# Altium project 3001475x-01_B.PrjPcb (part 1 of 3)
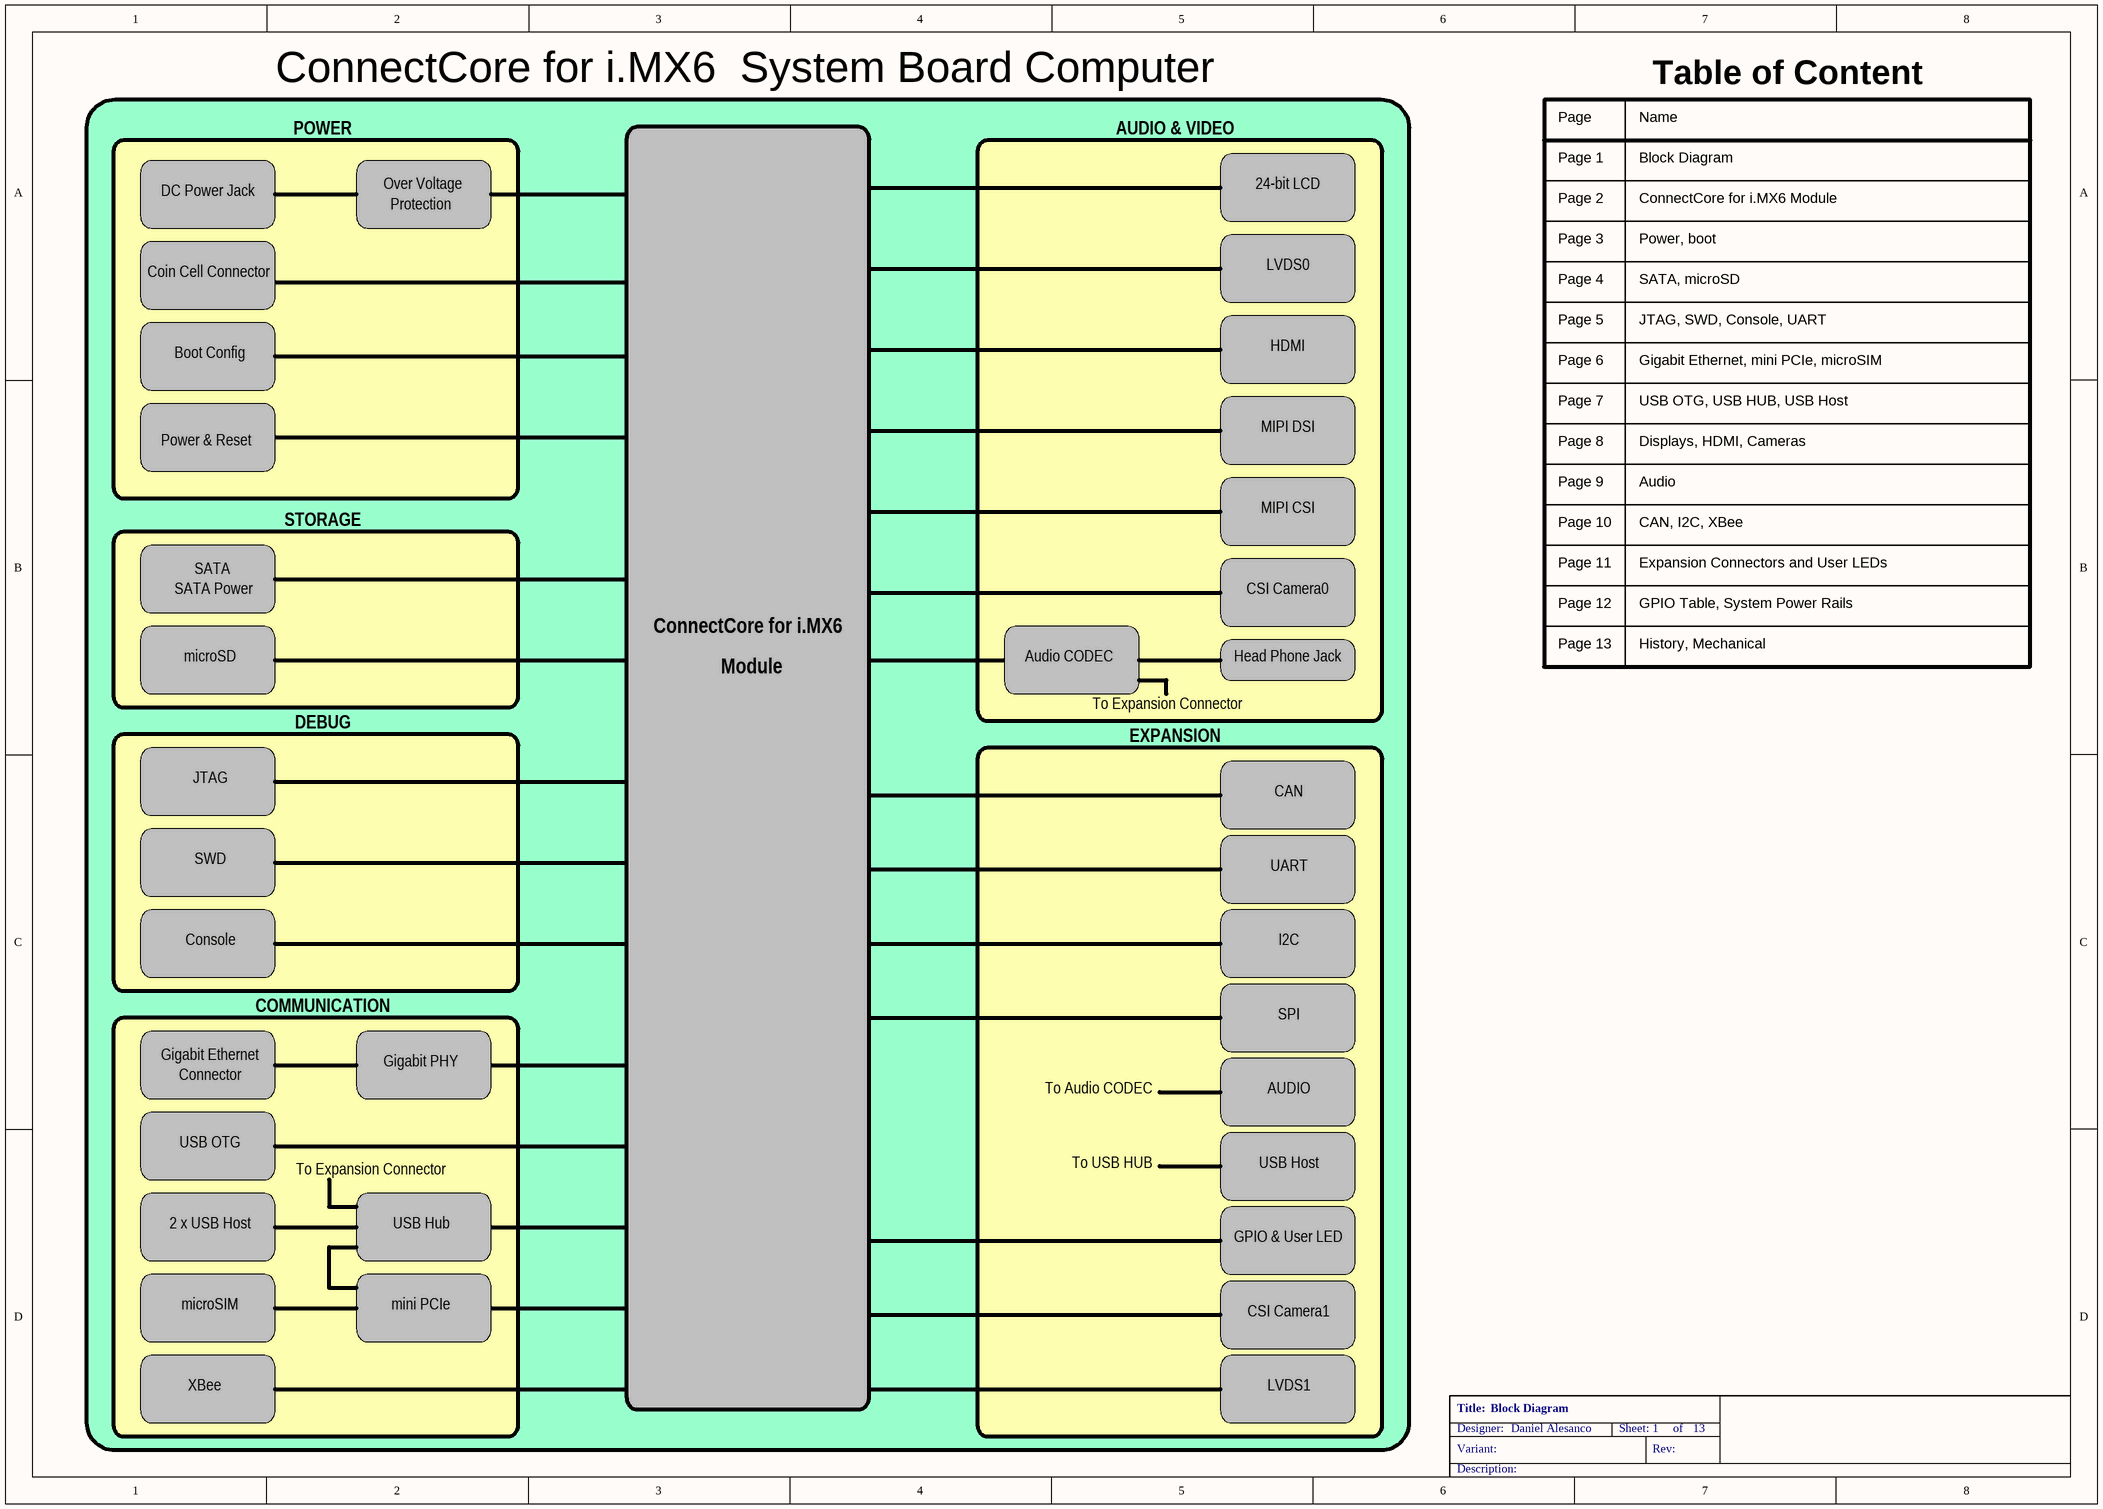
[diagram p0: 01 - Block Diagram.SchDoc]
13 sheets, 332 parts. Net scope: flat (ports and power ports of the same name join across sheets).
Board file: 3001475x-01_B.PcbDoc
Sheets:
  01 - Block Diagram.SchDoc
  02 - CCIMX6 Module.SchDoc
  03 - Power, Battery charger, boot.SchDoc
  04 - SATA, microSD.SchDoc
  05 - JTAG, SWD, Console, UART.SchDoc
  06 - Gigabit Ethernet, Mini PCIe, microSIM.SchDoc
  07 - USB OTG, USB HUB, USB Host.SchDoc
  08 - Displays, HDMI, Cameras.SchDoc
  09 - Audio.SchDoc
  10 - CAN, I2C, XBee.SchDoc
  11 - Expansion Connectors, User LEDs.SchDoc
  12 - GPIO Table, System Power rails.SchDoc
  13 - History, Mechanicals.SchDoc

## Sheet 01 - Block Diagram.SchDoc: Block Diagram
size A3; Author: Daniel Alesanco; Revision: 0.1; SheetNumber: 1; SheetTotal: 13; PageSetup: Record=PageOptions|CenterHorizontal=True|CenterVertical=True|PrintScale=0.70|XCorrection=1.00|YCorrection=1.00|PrintKind=0|BorderSize=5000000|LeftOffset=0|BottomOffset=0|Orientation=2|PaperLength=4200|PaperWidth=2970|Scale=100|PaperSource=7|PrintQuality=600|MediaType=1|DitherType=10|PaperKind=A4|PrintScaleMode=1

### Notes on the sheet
- ConnectCore for i.MX6  System Board Computer
- Table of Content
- POWER
- AUDIO & VIDEO
- Page 1
- Page
- Block Diagram
- Name
- DC Power Jack
- Over Voltage
- Protection
- 24-bit LCD
- Page 2
- Page 3
- ConnectCore for i.MX6 Module
- Power, boot
- Coin Cell Connector
- LVDS0
- Page 4
- SATA, microSD
- Boot Config
- HDMI
- Page 5
- Page 6
- Gigabit Ethernet, mini PCIe, microSIM
- JTAG, SWD, Console, UART
- Power & Reset
- MIPI DSI
- Page 7
- Page 8
- Displays, HDMI, Cameras
- USB OTG, USB HUB, USB Host
- MIPI CSI
- Page 9
- Audio
- SATA
- STORAGE
- Page 10
- Page 11
- CAN, I2C, XBee
- Expansion Connectors and User LEDs
- SATA Power
- ConnectCore for i.MX6
- CSI Camera0
- Page 12
- Page 13
- GPIO Table, System Power Rails
- History, Mechanical
- microSD
- Module
- Audio CODEC
- To Expansion Connector
- Head Phone Jack
- JTAG
- DEBUG
- EXPANSION
- CAN
- SWD
- UART
- Console
- I2C
- COMMUNICATION
- SPI
- Gigabit Ethernet
- Connector
- Gigabit PHY
- To Audio CODEC
- AUDIO
- USB OTG
- To USB HUB
- USB Host
- 2 x USB Host
- USB Hub
- GPIO & User LED
- microSIM
- mini PCIe
- CSI Camera1
- XBee
- LVDS1

## Sheet 02 - CCIMX6 Module.SchDoc: ConnectCore for i.MX6 Module
size A2; Author: Daniel Alesanco; Revision: 0.1; SheetNumber: 2; SheetTotal: 13; PageSetup: Record=PageOptions|CenterHorizontal=True|CenterVertical=True|PrintScale=0.71|XCorrection=1.00|YCorrection=1.00|PrintKind=0|BorderSize=5000000|LeftOffset=0|BottomOffset=0|Orientation=2|PaperLength=4200|PaperWidth=2970|Scale=100|PaperSource=7|PrintQuality=600|MediaType=1|DitherType=10|PaperKind=A3|PrintScaleMode=1
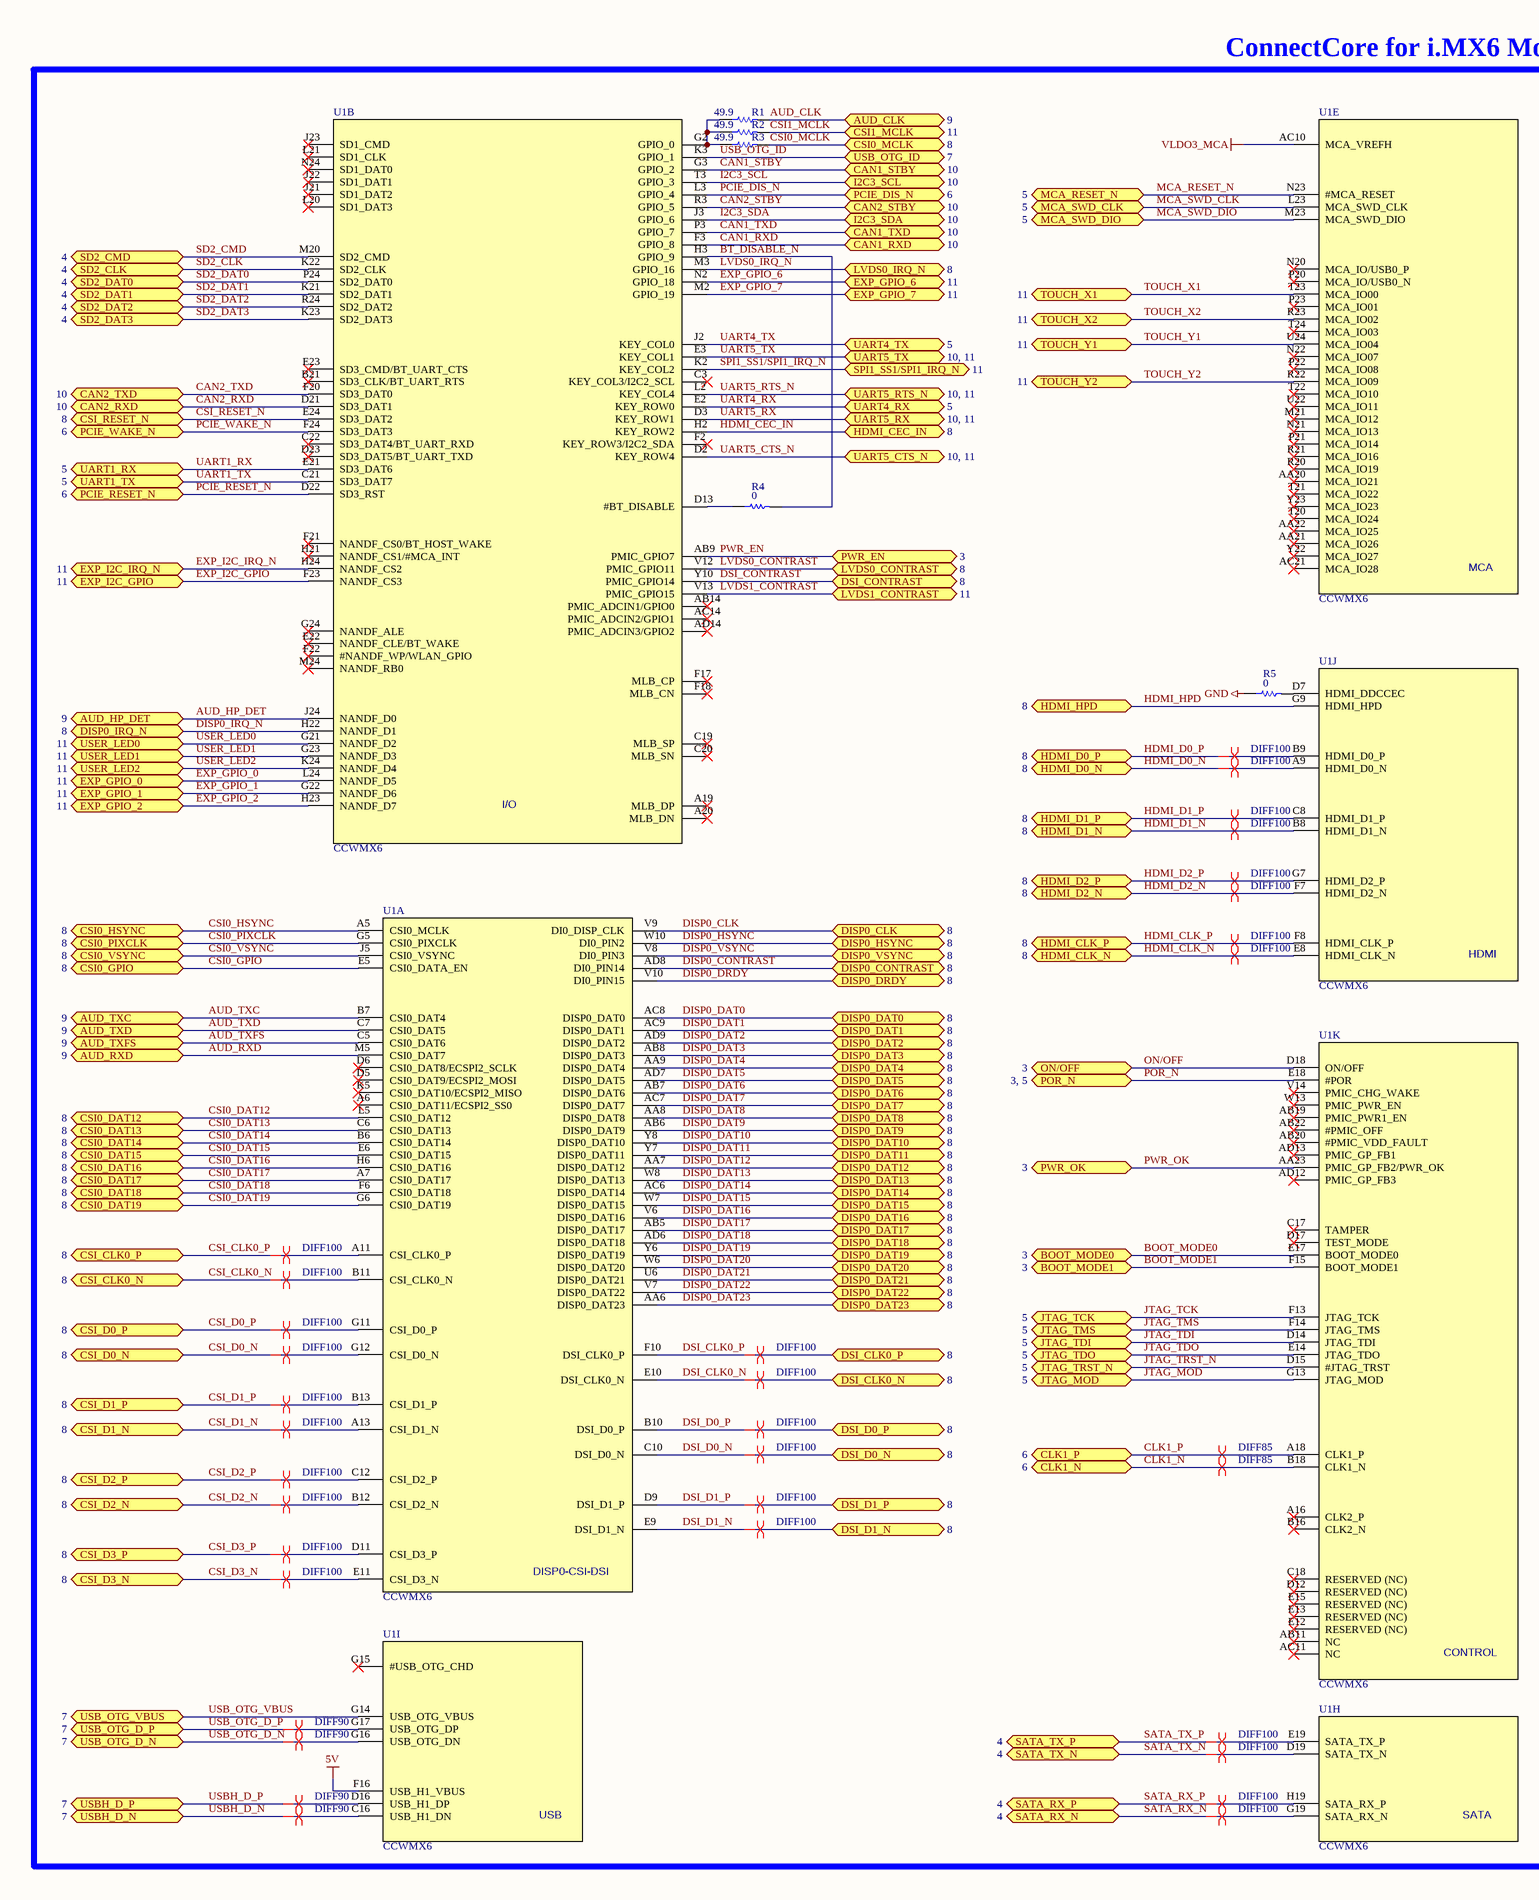
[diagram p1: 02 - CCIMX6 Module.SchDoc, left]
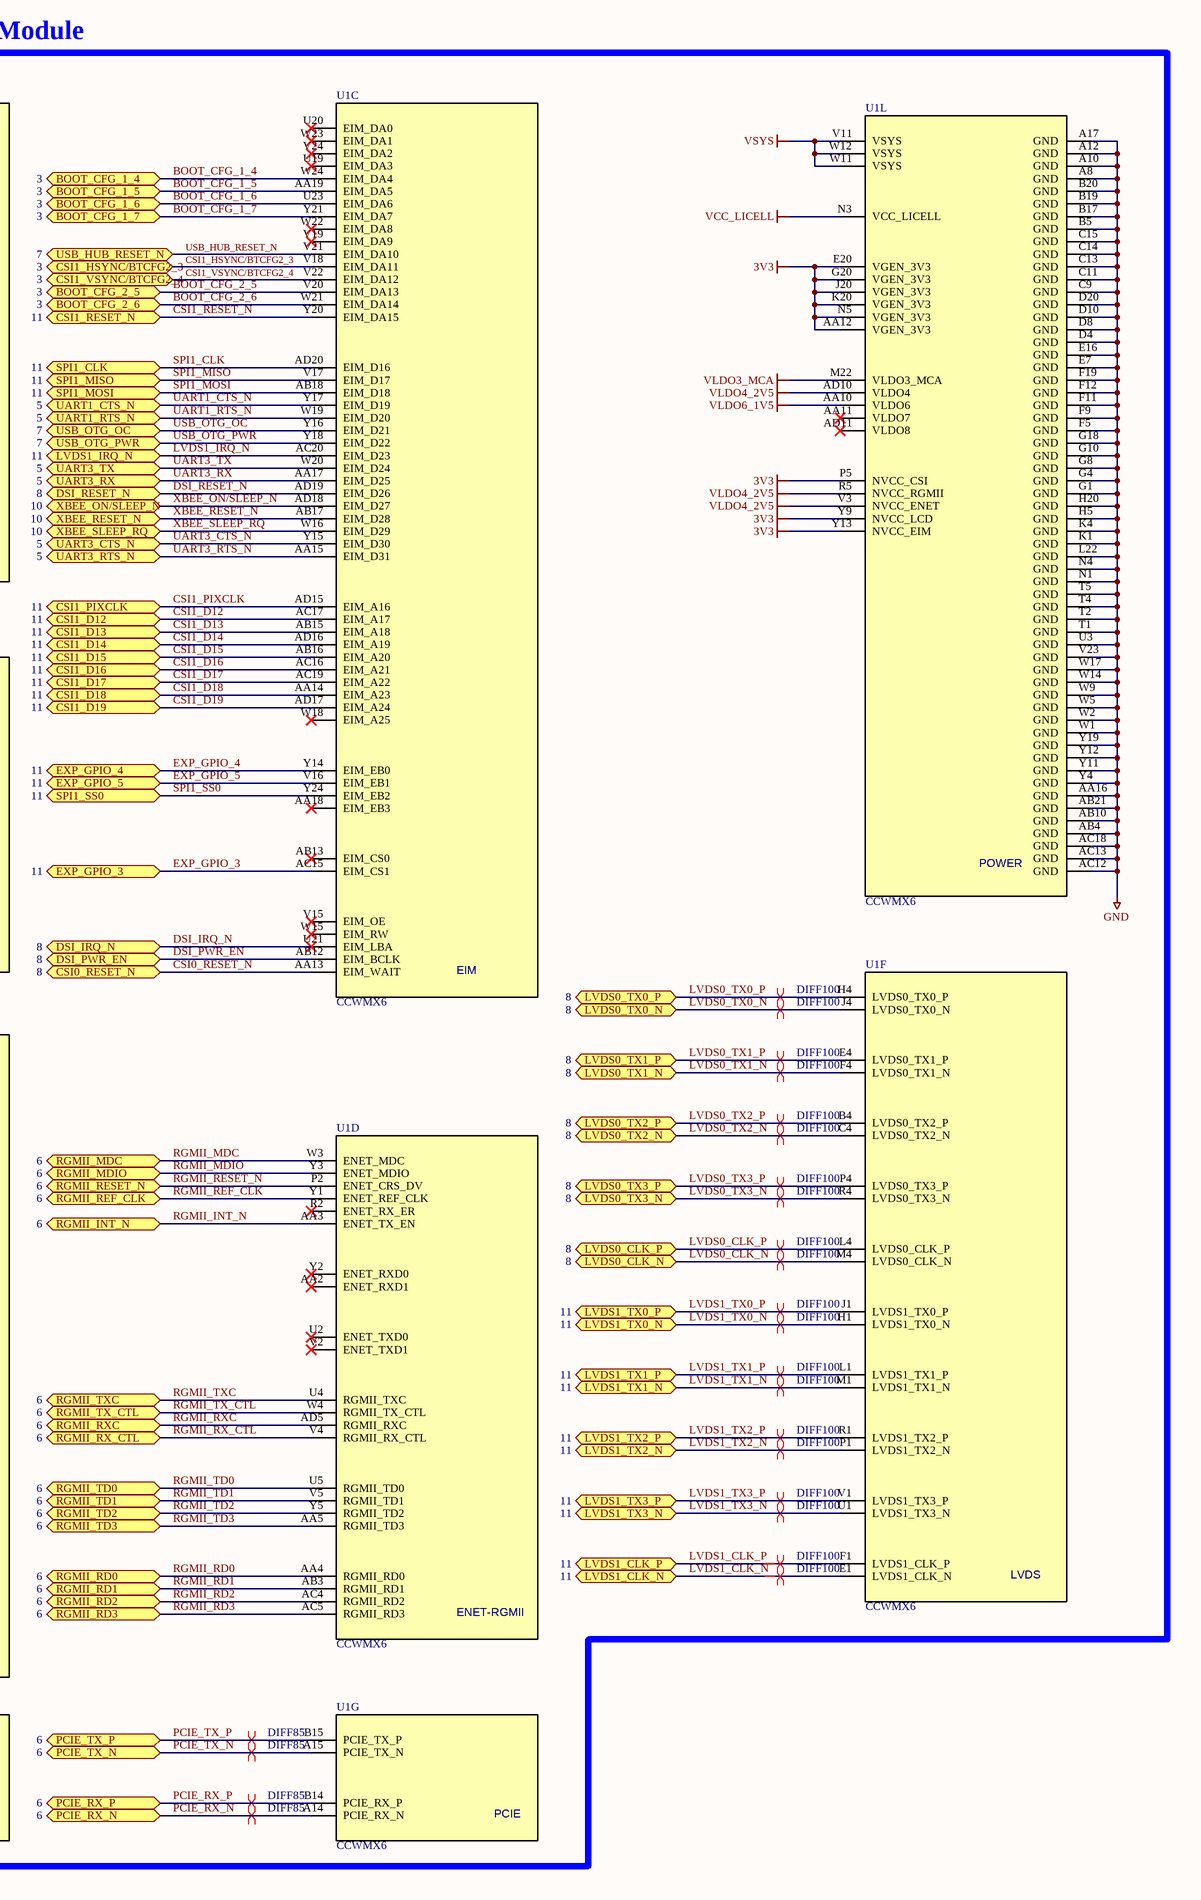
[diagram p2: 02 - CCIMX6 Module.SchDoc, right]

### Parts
R1  49.9  [RESC1005X40N]
R2  49.9  [RESC1005X40N]
R3  49.9  [RESC1005X40N]
R4  0  [RESC1005X40N]
R5  0  [RESC1005X40N]
U1  CCWMX6  [MODULE_30014822-XX]  (parts A,B,C,D,E,F,G,H,I,J,K,L of 12)

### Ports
AUD_CLK (bidir, see 9), AUD_HP_DET (bidir, see 9), AUD_RXD (bidir, see 9), AUD_TXC (bidir, see 9), AUD_TXD (bidir, see 9), AUD_TXFS (bidir, see 9), BOOT_CFG_1_4 (bidir, see 3), BOOT_CFG_1_5 (bidir, see 3), BOOT_CFG_1_6 (bidir, see 3), BOOT_CFG_1_7 (bidir, see 3), BOOT_CFG_2_5 (bidir, see 3), BOOT_CFG_2_6 (bidir, see 3), BOOT_MODE0 (bidir, see 3), BOOT_MODE1 (bidir, see 3), CAN1_RXD (bidir, see 10), CAN1_STBY (bidir, see 10), CAN1_TXD (bidir, see 10), CAN2_RXD (bidir, see 10), CAN2_STBY (bidir, see 10), CAN2_TXD (bidir, see 10), CLK1_N (bidir, see 6), CLK1_P (bidir, see 6), CSI0_DAT12 (bidir, see 8), CSI0_DAT13 (bidir, see 8), CSI0_DAT14 (bidir, see 8), CSI0_DAT15 (bidir, see 8), CSI0_DAT16 (bidir, see 8), CSI0_DAT17 (bidir, see 8), CSI0_DAT18 (bidir, see 8), CSI0_DAT19 (bidir, see 8), CSI0_GPIO (bidir, see 8), CSI0_HSYNC (bidir, see 8), CSI0_MCLK (bidir, see 8), CSI0_PIXCLK (bidir, see 8), CSI0_RESET_N (bidir, see 8), CSI0_VSYNC (bidir, see 8), CSI1_D12 (bidir, see 11), CSI1_D13 (bidir, see 11), CSI1_D14 (bidir, see 11), CSI1_D15 (bidir, see 11), CSI1_D16 (bidir, see 11), CSI1_D17 (bidir, see 11), CSI1_D18 (bidir, see 11), CSI1_D19 (bidir, see 11), CSI1_HSYNC/BTCFG2_3 (bidir, see 3), CSI1_MCLK (bidir, see 11), CSI1_PIXCLK (bidir, see 11), CSI1_RESET_N (bidir, see 11), CSI1_VSYNC/BTCFG2_4 (bidir, see 3), CSI_CLK0_N (bidir, see 8), CSI_CLK0_P (bidir, see 8), CSI_D0_N (bidir, see 8), CSI_D0_P (bidir, see 8), CSI_D1_N (bidir, see 8), CSI_D1_P (bidir, see 8), CSI_D2_N (bidir, see 8), CSI_D2_P (bidir, see 8), CSI_D3_N (bidir, see 8), CSI_D3_P (bidir, see 8), CSI_RESET_N (bidir, see 8), DISP0_CLK (bidir, see 8), DISP0_CONTRAST (bidir, see 8), DISP0_DAT0 (bidir, see 8), DISP0_DAT1 (bidir, see 8), DISP0_DAT2 (bidir, see 8), DISP0_DAT3 (bidir, see 8), DISP0_DAT4 (bidir, see 8), DISP0_DAT5 (bidir, see 8), DISP0_DAT6 (bidir, see 8), DISP0_DAT7 (bidir, see 8), DISP0_DAT8 (bidir, see 8), DISP0_DAT9 (bidir, see 8), DISP0_DAT10 (bidir, see 8), DISP0_DAT11 (bidir, see 8), DISP0_DAT12 (bidir, see 8), DISP0_DAT13 (bidir, see 8), DISP0_DAT14 (bidir, see 8), DISP0_DAT15 (bidir, see 8), DISP0_DAT16 (bidir, see 8), DISP0_DAT17 (bidir, see 8), DISP0_DAT18 (bidir, see 8), DISP0_DAT19 (bidir, see 8), DISP0_DAT20 (bidir, see 8), DISP0_DAT21 (bidir, see 8), DISP0_DAT22 (bidir, see 8), DISP0_DAT23 (bidir, see 8), DISP0_DRDY (bidir, see 8), DISP0_HSYNC (bidir, see 8), DISP0_IRQ_N (bidir, see 8), DISP0_VSYNC (bidir, see 8), DSI_CLK0_N (bidir, see 8), DSI_CLK0_P (bidir, see 8), DSI_CONTRAST (bidir, see 8), DSI_D0_N (bidir, see 8), DSI_D0_P (bidir, see 8), DSI_D1_N (bidir, see 8), DSI_D1_P (bidir, see 8), DSI_IRQ_N (bidir, see 8), DSI_PWR_EN (bidir, see 8), DSI_RESET_N (bidir, see 8), EXP_GPIO_0 (bidir, see 11), EXP_GPIO_1 (bidir, see 11), EXP_GPIO_2 (bidir, see 11), EXP_GPIO_3 (bidir, see 11), EXP_GPIO_4 (bidir, see 11), EXP_GPIO_5 (bidir, see 11), EXP_GPIO_6 (bidir, see 11), EXP_GPIO_7 (bidir, see 11), EXP_I2C_GPIO (bidir, see 11), EXP_I2C_IRQ_N (bidir, see 11), HDMI_CEC_IN (bidir, see 8), HDMI_CLK_N (bidir, see 8), HDMI_CLK_P (bidir, see 8), HDMI_D0_N (bidir, see 8), HDMI_D0_P (bidir, see 8), HDMI_D1_N (bidir, see 8), HDMI_D1_P (bidir, see 8), HDMI_D2_N (bidir, see 8), HDMI_D2_P (bidir, see 8), HDMI_HPD (bidir, see 8), I2C3_SCL (bidir, see 10), I2C3_SDA (bidir, see 10), JTAG_MOD (bidir, see 5), JTAG_TCK (bidir, see 5), JTAG_TDI (bidir, see 5), JTAG_TDO (bidir, see 5), JTAG_TMS (bidir, see 5), JTAG_TRST_N (bidir, see 5), LVDS0_CLK_N (bidir, see 8), LVDS0_CLK_P (bidir, see 8), LVDS0_CONTRAST (bidir, see 8), LVDS0_IRQ_N (bidir, see 8), LVDS0_TX0_N (bidir, see 8), LVDS0_TX0_P (bidir, see 8), LVDS0_TX1_N (bidir, see 8), LVDS0_TX1_P (bidir, see 8), LVDS0_TX2_N (bidir, see 8), LVDS0_TX2_P (bidir, see 8), LVDS0_TX3_N (bidir, see 8), LVDS0_TX3_P (bidir, see 8), LVDS1_CLK_N (bidir, see 11), LVDS1_CLK_P (bidir, see 11), LVDS1_CONTRAST (bidir, see 11), LVDS1_IRQ_N (bidir, see 11), LVDS1_TX0_N (bidir, see 11), LVDS1_TX0_P (bidir, see 11), LVDS1_TX1_N (bidir, see 11), LVDS1_TX1_P (bidir, see 11), LVDS1_TX2_N (bidir, see 11), LVDS1_TX2_P (bidir, see 11), LVDS1_TX3_N (bidir, see 11), LVDS1_TX3_P (bidir, see 11), MCA_RESET_N (bidir, see 5), MCA_SWD_CLK (bidir, see 5), MCA_SWD_DIO (bidir, see 5), ON/OFF (bidir, see 3), PCIE_DIS_N (bidir, see 6), PCIE_RESET_N (bidir, see 6), PCIE_RX_N (bidir, see 6), PCIE_RX_P (bidir, see 6), PCIE_TX_N (bidir, see 6), PCIE_TX_P (bidir, see 6), PCIE_WAKE_N (bidir, see 6), POR_N (bidir, see 3, 5), PWR_EN (bidir, see 3), PWR_OK (bidir, see 3), RGMII_INT_N (bidir, see 6), RGMII_MDC (bidir, see 6), RGMII_MDIO (bidir, see 6), RGMII_RD0 (bidir, see 6), RGMII_RD1 (bidir, see 6), RGMII_RD2 (bidir, see 6), RGMII_RD3 (bidir, see 6), RGMII_REF_CLK (bidir, see 6), RGMII_RESET_N (bidir, see 6), RGMII_RX_CTL (bidir, see 6), RGMII_RXC (bidir, see 6), RGMII_TD0 (bidir, see 6), RGMII_TD1 (bidir, see 6), RGMII_TD2 (bidir, see 6), RGMII_TD3 (bidir, see 6), RGMII_TX_CTL (bidir, see 6), RGMII_TXC (bidir, see 6), SATA_RX_N (bidir, see 4), SATA_RX_P (bidir, see 4), SATA_TX_N (bidir, see 4), SATA_TX_P (bidir, see 4), SD2_CLK (bidir, see 4), SD2_CMD (bidir, see 4), SD2_DAT0 (bidir, see 4), SD2_DAT1 (bidir, see 4), SD2_DAT2 (bidir, see 4), SD2_DAT3 (bidir, see 4), SPI1_CLK (bidir, see 11), SPI1_MISO (bidir, see 11), SPI1_MOSI (bidir, see 11), SPI1_SS0 (bidir, see 11), SPI1_SS1/SPI1_IRQ_N (bidir, see 11), TOUCH_X1 (bidir, see 11), TOUCH_X2 (bidir, see 11), TOUCH_Y1 (bidir, see 11), TOUCH_Y2 (bidir, see 11), UART1_CTS_N (bidir, see 5), UART1_RTS_N (bidir, see 5), UART1_RX (bidir, see 5), UART1_TX (bidir, see 5), UART3_CTS_N (bidir, see 5), UART3_RTS_N (bidir, see 5), UART3_RX (bidir, see 5), UART3_TX (bidir, see 5), UART4_RX (bidir, see 5), UART4_TX (bidir, see 5), UART5_CTS_N (bidir, see 10, 11), UART5_RTS_N (bidir, see 10, 11), UART5_RX (bidir, see 10, 11), UART5_TX (bidir, see 10, 11), USB_HUB_RESET_N (bidir, see 7), USB_OTG_D_N (bidir, see 7), USB_OTG_D_P (bidir, see 7), USB_OTG_ID (bidir, see 7), USB_OTG_OC (bidir, see 7), USB_OTG_PWR (bidir, see 7), USB_OTG_VBUS (bidir, see 7), USBH_D_N (bidir, see 7), USBH_D_P (bidir, see 7), USER_LED0 (bidir, see 11), USER_LED1 (bidir, see 11), USER_LED2 (bidir, see 11), XBEE_ON/SLEEP_N (bidir, see 10), XBEE_RESET_N (bidir, see 10), XBEE_SLEEP_RQ (bidir, see 10)

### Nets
3V3: U1.AA12(VGEN_3V3) U1.E20(VGEN_3V3) U1.G20(VGEN_3V3) U1.J20(VGEN_3V3) U1.K20(VGEN_3V3) U1.N5(VGEN_3V3) U1.P5(NVCC_CSI) U1.Y9(NVCC_LCD) U1.Y13(NVCC_EIM)
5V: U1.F16(USB_H1_VBUS)
GND: R5.1 U1.A8(GND) U1.A10(GND) U1.A12(GND) U1.A17(GND) U1.AA16(GND) U1.AB4(GND) U1.AB10(GND) U1.AB21(GND) U1.AC12(GND) U1.AC13(GND) U1.AC18(GND) U1.B5(GND) U1.B17(GND) U1.B19(GND) U1.B20(GND) U1.C9(GND) U1.C11(GND) U1.C13(GND) U1.C14(GND) U1.C15(GND) U1.D4(GND) U1.D8(GND) U1.D10(GND) U1.D20(GND) U1.E7(GND) U1.E16(GND) U1.F5(GND) U1.F9(GND) U1.F11(GND) U1.F12(GND) U1.F19(GND) U1.G1(GND) U1.G4(GND) U1.G8(GND) U1.G10(GND) U1.G18(GND) U1.H5(GND) U1.H20(GND) U1.K1(GND) U1.K4(GND) U1.L22(GND) U1.N1(GND) U1.N4(GND) U1.T1(GND) U1.T2(GND) U1.T4(GND) U1.T5(GND) U1.U3(GND) U1.V23(GND) U1.W1(GND) U1.W2(GND) U1.W5(GND) U1.W9(GND) U1.W14(GND) U1.W17(GND) U1.Y4(GND) U1.Y11(GND) U1.Y12(GND) U1.Y19(GND)
VCC_LICELL: U1.N3(VCC_LICELL)
VLDO3_MCA: U1.AC10(MCA_VREFH) U1.M22(VLDO3_MCA)
VLDO4_2V5: U1.AD10(VLDO4) U1.R5(NVCC_RGMII) U1.V3(NVCC_ENET)
VLDO6_1V5: U1.AA10(VLDO6)
VSYS: U1.V11(VSYS) U1.W11(VSYS) U1.W12(VSYS)
AUD_CLK: R1.2 ; port AUD_CLK
AUD_HP_DET: U1.J24(NANDF_D0) ; port AUD_HP_DET
AUD_RXD: U1.M5(CSI0_DAT7) ; port AUD_RXD
AUD_TXC: U1.B7(CSI0_DAT4) ; port AUD_TXC
AUD_TXD: U1.C7(CSI0_DAT5) ; port AUD_TXD
AUD_TXFS: U1.C5(CSI0_DAT6) ; port AUD_TXFS
BOOT_CFG_1_4: U1.W24(EIM_DA4) ; port BOOT_CFG_1_4
BOOT_CFG_1_5: U1.AA19(EIM_DA5) ; port BOOT_CFG_1_5
BOOT_CFG_1_6: U1.U23(EIM_DA6) ; port BOOT_CFG_1_6
BOOT_CFG_1_7: U1.Y21(EIM_DA7) ; port BOOT_CFG_1_7
BOOT_CFG_2_5: U1.V20(EIM_DA13) ; port BOOT_CFG_2_5
BOOT_CFG_2_6: U1.W21(EIM_DA14) ; port BOOT_CFG_2_6
BOOT_MODE0: U1.E17(BOOT_MODE0) ; port BOOT_MODE0
BOOT_MODE1: U1.F15(BOOT_MODE1) ; port BOOT_MODE1
BT_DISABLE_N: R4.2 U1.H3(GPIO_9)
CAN1_RXD: U1.F3(GPIO_8) ; port CAN1_RXD
CAN1_STBY: U1.G3(GPIO_2) ; port CAN1_STBY
CAN1_TXD: U1.P3(GPIO_7) ; port CAN1_TXD
CAN2_RXD: U1.D21(SD3_DAT1) ; port CAN2_RXD
CAN2_STBY: U1.R3(GPIO_5) ; port CAN2_STBY
CAN2_TXD: U1.F20(SD3_DAT0) ; port CAN2_TXD
CLK1_N: U1.B18(CLK1_N) ; port CLK1_N
CLK1_P: U1.A18(CLK1_P) ; port CLK1_P
CSI0_DAT12: U1.L5(CSI0_DAT12) ; port CSI0_DAT12
CSI0_DAT13: U1.C6(CSI0_DAT13) ; port CSI0_DAT13
CSI0_DAT14: U1.B6(CSI0_DAT14) ; port CSI0_DAT14
CSI0_DAT15: U1.E6(CSI0_DAT15) ; port CSI0_DAT15
CSI0_DAT16: U1.H6(CSI0_DAT16) ; port CSI0_DAT16
CSI0_DAT17: U1.A7(CSI0_DAT17) ; port CSI0_DAT17
CSI0_DAT18: U1.F6(CSI0_DAT18) ; port CSI0_DAT18
CSI0_DAT19: U1.G6(CSI0_DAT19) ; port CSI0_DAT19
CSI0_GPIO: U1.E5(CSI0_DATA_EN) ; port CSI0_GPIO
CSI0_HSYNC: U1.A5(CSI0_MCLK) ; port CSI0_HSYNC
CSI0_MCLK: R3.2 ; port CSI0_MCLK
CSI0_PIXCLK: U1.G5(CSI0_PIXCLK) ; port CSI0_PIXCLK
CSI0_RESET_N: U1.AA13(EIM_WAIT) ; port CSI0_RESET_N
CSI0_VSYNC: U1.J5(CSI0_VSYNC) ; port CSI0_VSYNC
CSI1_D12: U1.AC17(EIM_A17) ; port CSI1_D12
CSI1_D13: U1.AB15(EIM_A18) ; port CSI1_D13
CSI1_D14: U1.AD16(EIM_A19) ; port CSI1_D14
CSI1_D15: U1.AB16(EIM_A20) ; port CSI1_D15
CSI1_D16: U1.AC16(EIM_A21) ; port CSI1_D16
CSI1_D17: U1.AC19(EIM_A22) ; port CSI1_D17
CSI1_D18: U1.AA14(EIM_A23) ; port CSI1_D18
CSI1_D19: U1.AD17(EIM_A24) ; port CSI1_D19
CSI1_HSYNC/BTCFG2_3: U1.V18(EIM_DA11) ; port CSI1_HSYNC/BTCFG2_3
CSI1_MCLK: R2.2 ; port CSI1_MCLK
CSI1_PIXCLK: U1.AD15(EIM_A16) ; port CSI1_PIXCLK
CSI1_RESET_N: U1.Y20(EIM_DA15) ; port CSI1_RESET_N
CSI1_VSYNC/BTCFG2_4: U1.V22(EIM_DA12) ; port CSI1_VSYNC/BTCFG2_4
CSI_CLK0_N: U1.B11(CSI_CLK0_N) ; port CSI_CLK0_N
CSI_CLK0_P: U1.A11(CSI_CLK0_P) ; port CSI_CLK0_P
CSI_D0_N: U1.G12(CSI_D0_N) ; port CSI_D0_N
CSI_D0_P: U1.G11(CSI_D0_P) ; port CSI_D0_P
CSI_D1_N: U1.A13(CSI_D1_N) ; port CSI_D1_N
CSI_D1_P: U1.B13(CSI_D1_P) ; port CSI_D1_P
CSI_D2_N: U1.B12(CSI_D2_N) ; port CSI_D2_N
CSI_D2_P: U1.C12(CSI_D2_P) ; port CSI_D2_P
CSI_D3_N: U1.E11(CSI_D3_N) ; port CSI_D3_N
CSI_D3_P: U1.D11(CSI_D3_P) ; port CSI_D3_P
CSI_RESET_N: U1.E24(SD3_DAT2) ; port CSI_RESET_N
DISP0_CLK: U1.V9(DI0_DISP_CLK) ; port DISP0_CLK
DISP0_CONTRAST: U1.AD8(DI0_PIN14) ; port DISP0_CONTRAST
DISP0_DAT0: U1.AC8(DISP0_DAT0) ; port DISP0_DAT0
DISP0_DAT1: U1.AC9(DISP0_DAT1) ; port DISP0_DAT1
DISP0_DAT2: U1.AD9(DISP0_DAT2) ; port DISP0_DAT2
DISP0_DAT3: U1.AB8(DISP0_DAT3) ; port DISP0_DAT3
DISP0_DAT4: U1.AA9(DISP0_DAT4) ; port DISP0_DAT4
DISP0_DAT5: U1.AD7(DISP0_DAT5) ; port DISP0_DAT5
DISP0_DAT6: U1.AB7(DISP0_DAT6) ; port DISP0_DAT6
DISP0_DAT7: U1.AC7(DISP0_DAT7) ; port DISP0_DAT7
DISP0_DAT8: U1.AA8(DISP0_DAT8) ; port DISP0_DAT8
DISP0_DAT9: U1.AB6(DISP0_DAT9) ; port DISP0_DAT9
DISP0_DAT10: U1.Y8(DISP0_DAT10) ; port DISP0_DAT10
DISP0_DAT11: U1.Y7(DISP0_DAT11) ; port DISP0_DAT11
DISP0_DAT12: U1.AA7(DISP0_DAT12) ; port DISP0_DAT12
DISP0_DAT13: U1.W8(DISP0_DAT13) ; port DISP0_DAT13
DISP0_DAT14: U1.AC6(DISP0_DAT14) ; port DISP0_DAT14
DISP0_DAT15: U1.W7(DISP0_DAT15) ; port DISP0_DAT15
DISP0_DAT16: U1.V6(DISP0_DAT16) ; port DISP0_DAT16
DISP0_DAT17: U1.AB5(DISP0_DAT17) ; port DISP0_DAT17
DISP0_DAT18: U1.AD6(DISP0_DAT18) ; port DISP0_DAT18
DISP0_DAT19: U1.Y6(DISP0_DAT19) ; port DISP0_DAT19
DISP0_DAT20: U1.W6(DISP0_DAT20) ; port DISP0_DAT20
DISP0_DAT21: U1.U6(DISP0_DAT21) ; port DISP0_DAT21
DISP0_DAT22: U1.V7(DISP0_DAT22) ; port DISP0_DAT22
DISP0_DAT23: U1.AA6(DISP0_DAT23) ; port DISP0_DAT23
DISP0_DRDY: U1.V10(DI0_PIN15) ; port DISP0_DRDY
DISP0_HSYNC: U1.W10(DI0_PIN2) ; port DISP0_HSYNC
DISP0_IRQ_N: U1.H22(NANDF_D1) ; port DISP0_IRQ_N
DISP0_VSYNC: U1.V8(DI0_PIN3) ; port DISP0_VSYNC
DSI_CLK0_N: U1.E10(DSI_CLK0_N) ; port DSI_CLK0_N
DSI_CLK0_P: U1.F10(DSI_CLK0_P) ; port DSI_CLK0_P
DSI_CONTRAST: U1.Y10(PMIC_GPIO14) ; port DSI_CONTRAST
DSI_D0_N: U1.C10(DSI_D0_N) ; port DSI_D0_N
DSI_D0_P: U1.B10(DSI_D0_P) ; port DSI_D0_P
DSI_D1_N: U1.E9(DSI_D1_N) ; port DSI_D1_N
DSI_D1_P: U1.D9(DSI_D1_P) ; port DSI_D1_P
DSI_IRQ_N: U1.U21(EIM_LBA) ; port DSI_IRQ_N
DSI_PWR_EN: U1.AB12(EIM_BCLK) ; port DSI_PWR_EN
DSI_RESET_N: U1.AD19(EIM_D26) ; port DSI_RESET_N
EXP_GPIO_0: U1.L24(NANDF_D5) ; port EXP_GPIO_0
EXP_GPIO_1: U1.G22(NANDF_D6) ; port EXP_GPIO_1
EXP_GPIO_2: U1.H23(NANDF_D7) ; port EXP_GPIO_2
EXP_GPIO_3: U1.AC15(EIM_CS1) ; port EXP_GPIO_3
EXP_GPIO_4: U1.Y14(EIM_EB0) ; port EXP_GPIO_4
EXP_GPIO_5: U1.V16(EIM_EB1) ; port EXP_GPIO_5
EXP_GPIO_6: U1.N2(GPIO_18) ; port EXP_GPIO_6
EXP_GPIO_7: U1.M2(GPIO_19) ; port EXP_GPIO_7
EXP_I2C_GPIO: U1.F23(NANDF_CS3) ; port EXP_I2C_GPIO
EXP_I2C_IRQ_N: U1.H24(NANDF_CS2) ; port EXP_I2C_IRQ_N
HDMI_CEC_IN: U1.H2(KEY_ROW2) ; port HDMI_CEC_IN
HDMI_CLK_N: U1.E8(HDMI_CLK_N) ; port HDMI_CLK_N
HDMI_CLK_P: U1.F8(HDMI_CLK_P) ; port HDMI_CLK_P
HDMI_D0_N: U1.A9(HDMI_D0_N) ; port HDMI_D0_N
HDMI_D0_P: U1.B9(HDMI_D0_P) ; port HDMI_D0_P
HDMI_D1_N: U1.B8(HDMI_D1_N) ; port HDMI_D1_N
HDMI_D1_P: U1.C8(HDMI_D1_P) ; port HDMI_D1_P
HDMI_D2_N: U1.F7(HDMI_D2_N) ; port HDMI_D2_N
HDMI_D2_P: U1.G7(HDMI_D2_P) ; port HDMI_D2_P
HDMI_HPD: U1.G9(HDMI_HPD) ; port HDMI_HPD
I2C3_SCL: U1.T3(GPIO_3) ; port I2C3_SCL
I2C3_SDA: U1.J3(GPIO_6) ; port I2C3_SDA
JTAG_MOD: U1.G13(JTAG_MOD) ; port JTAG_MOD
JTAG_TCK: U1.F13(JTAG_TCK) ; port JTAG_TCK
JTAG_TDI: U1.D14(JTAG_TDI) ; port JTAG_TDI
JTAG_TDO: U1.E14(JTAG_TDO) ; port JTAG_TDO
JTAG_TMS: U1.F14(JTAG_TMS) ; port JTAG_TMS
JTAG_TRST_N: U1.D15(#JTAG_TRST) ; port JTAG_TRST_N
LVDS0_CLK_N: U1.M4(LVDS0_CLK_N) ; port LVDS0_CLK_N
LVDS0_CLK_P: U1.L4(LVDS0_CLK_P) ; port LVDS0_CLK_P
LVDS0_CONTRAST: U1.V12(PMIC_GPIO11) ; port LVDS0_CONTRAST
LVDS0_IRQ_N: U1.M3(GPIO_16) ; port LVDS0_IRQ_N
LVDS0_TX0_N: U1.J4(LVDS0_TX0_N) ; port LVDS0_TX0_N
LVDS0_TX0_P: U1.H4(LVDS0_TX0_P) ; port LVDS0_TX0_P
LVDS0_TX1_N: U1.F4(LVDS0_TX1_N) ; port LVDS0_TX1_N
LVDS0_TX1_P: U1.E4(LVDS0_TX1_P) ; port LVDS0_TX1_P
LVDS0_TX2_N: U1.C4(LVDS0_TX2_N) ; port LVDS0_TX2_N
LVDS0_TX2_P: U1.B4(LVDS0_TX2_P) ; port LVDS0_TX2_P
LVDS0_TX3_N: U1.R4(LVDS0_TX3_N) ; port LVDS0_TX3_N
LVDS0_TX3_P: U1.P4(LVDS0_TX3_P) ; port LVDS0_TX3_P
LVDS1_CLK_N: U1.E1(LVDS1_CLK_N) ; port LVDS1_CLK_N
LVDS1_CLK_P: U1.F1(LVDS1_CLK_P) ; port LVDS1_CLK_P
LVDS1_CONTRAST: U1.V13(PMIC_GPIO15) ; port LVDS1_CONTRAST
LVDS1_IRQ_N: U1.AC20(EIM_D23) ; port LVDS1_IRQ_N
LVDS1_TX0_N: U1.H1(LVDS1_TX0_N) ; port LVDS1_TX0_N
LVDS1_TX0_P: U1.J1(LVDS1_TX0_P) ; port LVDS1_TX0_P
LVDS1_TX1_N: U1.M1(LVDS1_TX1_N) ; port LVDS1_TX1_N
LVDS1_TX1_P: U1.L1(LVDS1_TX1_P) ; port LVDS1_TX1_P
LVDS1_TX2_N: U1.P1(LVDS1_TX2_N) ; port LVDS1_TX2_N
LVDS1_TX2_P: U1.R1(LVDS1_TX2_P) ; port LVDS1_TX2_P
LVDS1_TX3_N: U1.U1(LVDS1_TX3_N) ; port LVDS1_TX3_N
LVDS1_TX3_P: U1.V1(LVDS1_TX3_P) ; port LVDS1_TX3_P
MCA_RESET_N: U1.N23(#MCA_RESET) ; port MCA_RESET_N
MCA_SWD_CLK: U1.L23(MCA_SWD_CLK) ; port MCA_SWD_CLK
MCA_SWD_DIO: U1.M23(MCA_SWD_DIO) ; port MCA_SWD_DIO
ON/OFF: U1.D18(ON/OFF) ; port ON/OFF
PCIE_DIS_N: U1.L3(GPIO_4) ; port PCIE_DIS_N
PCIE_RESET_N: U1.D22(SD3_RST) ; port PCIE_RESET_N
PCIE_RX_N: U1.A14(PCIE_RX_N) ; port PCIE_RX_N
PCIE_RX_P: U1.B14(PCIE_RX_P) ; port PCIE_RX_P
PCIE_TX_N: U1.A15(PCIE_TX_N) ; port PCIE_TX_N
PCIE_TX_P: U1.B15(PCIE_TX_P) ; port PCIE_TX_P
PCIE_WAKE_N: U1.F24(SD3_DAT3) ; port PCIE_WAKE_N
POR_N: U1.E18(#POR) ; port POR_N
PWR_EN: U1.AB9(PMIC_GPIO7) ; port PWR_EN
PWR_OK: U1.AA23(PMIC_GP_FB2/PWR_OK) ; port PWR_OK
RGMII_INT_N: U1.AA3(ENET_TX_EN) ; port RGMII_INT_N
RGMII_MDC: U1.W3(ENET_MDC) ; port RGMII_MDC
RGMII_MDIO: U1.Y3(ENET_MDIO) ; port RGMII_MDIO
RGMII_RD0: U1.AA4(RGMII_RD0) ; port RGMII_RD0
RGMII_RD1: U1.AB3(RGMII_RD1) ; port RGMII_RD1
RGMII_RD2: U1.AC4(RGMII_RD2) ; port RGMII_RD2
RGMII_RD3: U1.AC5(RGMII_RD3) ; port RGMII_RD3
RGMII_REF_CLK: U1.Y1(ENET_REF_CLK) ; port RGMII_REF_CLK
RGMII_RESET_N: U1.P2(ENET_CRS_DV) ; port RGMII_RESET_N
RGMII_RX_CTL: U1.V4(RGMII_RX_CTL) ; port RGMII_RX_CTL
RGMII_RXC: U1.AD5(RGMII_RXC) ; port RGMII_RXC
RGMII_TD0: U1.U5(RGMII_TD0) ; port RGMII_TD0
RGMII_TD1: U1.V5(RGMII_TD1) ; port RGMII_TD1
RGMII_TD2: U1.Y5(RGMII_TD2) ; port RGMII_TD2
RGMII_TD3: U1.AA5(RGMII_TD3) ; port RGMII_TD3
RGMII_TX_CTL: U1.W4(RGMII_TX_CTL) ; port RGMII_TX_CTL
RGMII_TXC: U1.U4(RGMII_TXC) ; port RGMII_TXC
SATA_RX_N: U1.G19(SATA_RX_N) ; port SATA_RX_N
SATA_RX_P: U1.H19(SATA_RX_P) ; port SATA_RX_P
SATA_TX_N: U1.D19(SATA_TX_N) ; port SATA_TX_N
SATA_TX_P: U1.E19(SATA_TX_P) ; port SATA_TX_P
SD2_CLK: U1.K22(SD2_CLK) ; port SD2_CLK
SD2_CMD: U1.M20(SD2_CMD) ; port SD2_CMD
SD2_DAT0: U1.P24(SD2_DAT0) ; port SD2_DAT0
SD2_DAT1: U1.K21(SD2_DAT1) ; port SD2_DAT1
SD2_DAT2: U1.R24(SD2_DAT2) ; port SD2_DAT2
SD2_DAT3: U1.K23(SD2_DAT3) ; port SD2_DAT3
SPI1_CLK: U1.AD20(EIM_D16) ; port SPI1_CLK
SPI1_MISO: U1.V17(EIM_D17) ; port SPI1_MISO
SPI1_MOSI: U1.AB18(EIM_D18) ; port SPI1_MOSI
SPI1_SS0: U1.Y24(EIM_EB2) ; port SPI1_SS0
SPI1_SS1/SPI1_IRQ_N: U1.K2(KEY_COL2) ; port SPI1_SS1/SPI1_IRQ_N
TOUCH_X1: U1.T23(MCA_IO00) ; port TOUCH_X1
TOUCH_X2: U1.R23(MCA_IO02) ; port TOUCH_X2
TOUCH_Y1: U1.U24(MCA_IO04) ; port TOUCH_Y1
TOUCH_Y2: U1.R22(MCA_IO09) ; port TOUCH_Y2
UART1_CTS_N: U1.Y17(EIM_D19) ; port UART1_CTS_N
UART1_RTS_N: U1.W19(EIM_D20) ; port UART1_RTS_N
UART1_RX: U1.E21(SD3_DAT6) ; port UART1_RX
UART1_TX: U1.C21(SD3_DAT7) ; port UART1_TX
UART3_CTS_N: U1.Y15(EIM_D30) ; port UART3_CTS_N
UART3_RTS_N: U1.AA15(EIM_D31) ; port UART3_RTS_N
UART3_RX: U1.AA17(EIM_D25) ; port UART3_RX
UART3_TX: U1.W20(EIM_D24) ; port UART3_TX
UART4_RX: U1.E2(KEY_ROW0) ; port UART4_RX
UART4_TX: U1.J2(KEY_COL0) ; port UART4_TX
UART5_CTS_N: U1.D2(KEY_ROW4) ; port UART5_CTS_N
UART5_RTS_N: U1.L2(KEY_COL4) ; port UART5_RTS_N
UART5_RX: U1.D3(KEY_ROW1) ; port UART5_RX
UART5_TX: U1.E3(KEY_COL1) ; port UART5_TX
USB_HUB_RESET_N: U1.V21(EIM_DA10) ; port USB_HUB_RESET_N
USB_OTG_D_N: U1.G16(USB_OTG_DN) ; port USB_OTG_D_N
USB_OTG_D_P: U1.G17(USB_OTG_DP) ; port USB_OTG_D_P
USB_OTG_ID: U1.K3(GPIO_1) ; port USB_OTG_ID
USB_OTG_OC: U1.Y16(EIM_D21) ; port USB_OTG_OC
USB_OTG_PWR: U1.Y18(EIM_D22) ; port USB_OTG_PWR
USB_OTG_VBUS: U1.G14(USB_OTG_VBUS) ; port USB_OTG_VBUS
USBH_D_N: U1.C16(USB_H1_DN) ; port USBH_D_N
USBH_D_P: U1.D16(USB_H1_DP) ; port USBH_D_P
USER_LED0: U1.G21(NANDF_D2) ; port USER_LED0
USER_LED1: U1.G23(NANDF_D3) ; port USER_LED1
USER_LED2: U1.K24(NANDF_D4) ; port USER_LED2
XBEE_ON/SLEEP_N: U1.AD18(EIM_D27) ; port XBEE_ON/SLEEP_N
XBEE_RESET_N: U1.AB17(EIM_D28) ; port XBEE_RESET_N
XBEE_SLEEP_RQ: U1.W16(EIM_D29) ; port XBEE_SLEEP_RQ
NetR1_1: R1.1 R2.1 R3.1 U1.G2(GPIO_0)
NetR4_1: R4.1 U1.D13(#BT_DISABLE)
NetR5_2: R5.2 U1.D7(HDMI_DDCCEC)

Not connected (* = marked no-connect by the designer): U1 A6(CSI0_DAT11/ECSPI2_SS0)* A16(CLK2_P)* A19(MLB_DP)* A20(MLB_DN)* AA2(ENET_RXD1)* AA11(VLDO7)* AA18(EIM_EB3)* AA20(MCA_IO21)* AA21(MCA_IO26)* AA22(MCA_IO25)* AB11(NC)* AB13(EIM_CS0)* AB14(PMIC_ADCIN1/GPIO0)* AB19(PMIC_PWR1_EN)* AB20(#PMIC_VDD_FAULT)* AB22(#PMIC_OFF)* AC11(NC)* AC14(PMIC_ADCIN2/GPIO1)* AC21(MCA_IO28)* AD11(VLDO8)* AD12(PMIC_GP_FB3)* AD13(PMIC_GP_FB1)* AD14(PMIC_ADCIN3/GPIO2)* B16(CLK2_N)* B21(SD3_CLK/BT_UART_RTS)* C3(KEY_COL3/I2C2_SCL)* C17(TAMPER)* C18(RESERVED_(NC))* C19(MLB_SP)* C20(MLB_SN)* C22(SD3_DAT4/BT_UART_RXD)* D5(CSI0_DAT9/ECSPI2_MOSI)* D6(CSI0_DAT8/ECSPI2_SCLK)* D12(RESERVED_(NC))* D17(TEST_MODE)* D23(SD3_DAT5/BT_UART_TXD)* E12(RESERVED_(NC))* E13(RESERVED_(NC))* E15(RESERVED_(NC))* E22(NANDF_CLE/BT_WAKE)* E23(SD3_CMD/BT_UART_CTS)* F2(KEY_ROW3/I2C2_SDA)* F17(MLB_CP)* F18(MLB_CN)* F21(NANDF_CS0/BT_HOST_WAKE)* F22(#NANDF_WP/WLAN_GPIO)* G15(#USB_OTG_CHD)* G24(NANDF_ALE)* H21(NANDF_CS1/#MCA_INT)* J21(SD1_DAT2)* J22(SD1_DAT1)* J23(SD1_CMD)* K5(CSI0_DAT10/ECSPI2_MISO)* L20(SD1_DAT3)* L21(SD1_CLK)* M21(MCA_IO12)* M24(NANDF_RB0)* N20(MCA_IO/USB0_P)* N21(MCA_IO13)* N22(MCA_IO07)* N24(SD1_DAT0)* P20(MCA_IO/USB0_N)* P21(MCA_IO14)* P22(MCA_IO08)* P23(MCA_IO01)* R2(ENET_RX_ER)* R20(MCA_IO19)* R21(MCA_IO16)* T20(MCA_IO24)* T21(MCA_IO22)* T22(MCA_IO10)* T24(MCA_IO03)* U2(ENET_TXD0)* U19(EIM_DA3)* U20(EIM_DA0)* U22(MCA_IO11)* V2(ENET_TXD1)* V14(PMIC_CHG_WAKE)* V15(EIM_OE)* V19(EIM_DA9)* V24(EIM_DA2)* W13(PMIC_PWR_EN)* W15(EIM_RW)* W18(EIM_A25)* W22(EIM_DA8)* W23(EIM_DA1)* Y2(ENET_RXD0)* Y22(MCA_IO27)* Y23(MCA_IO23)*

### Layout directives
differential pair; net class DIFF100: CSI_CLK0_N, CSI_CLK0_P, CSI_D0_N, CSI_D0_P, CSI_D1_N, CSI_D1_P, CSI_D2_N, CSI_D2_P, CSI_D3_N, CSI_D3_P, DSI_CLK0_N, DSI_CLK0_P, DSI_D0_N, DSI_D0_P, DSI_D1_N, DSI_D1_P, HDMI_CLK_N, HDMI_CLK_P, HDMI_D0_N, HDMI_D0_P, HDMI_D1_N, HDMI_D1_P, HDMI_D2_N, HDMI_D2_P, LVDS0_CLK_N, LVDS0_CLK_P, LVDS0_TX0_N, LVDS0_TX0_P, LVDS0_TX1_N, LVDS0_TX1_P, LVDS0_TX2_N, LVDS0_TX2_P, LVDS0_TX3_N, LVDS0_TX3_P, LVDS1_CLK_N, LVDS1_CLK_P, LVDS1_TX0_N, LVDS1_TX0_P, LVDS1_TX1_N, LVDS1_TX1_P, LVDS1_TX2_N, LVDS1_TX2_P, LVDS1_TX3_N, LVDS1_TX3_P, SATA_RX_N, SATA_RX_P, SATA_TX_N, SATA_TX_P
differential pair; net class DIFF90: USB_OTG_D_N, USB_OTG_D_P, USBH_D_N, USBH_D_P
differential pair; net class DIFF85: CLK1_N, CLK1_P, PCIE_RX_N, PCIE_RX_P, PCIE_TX_N, PCIE_TX_P

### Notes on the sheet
- ConnectCore for i.MX6 Module

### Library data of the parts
R1-R3 = 1000466: RES 49.9 OHM 1/10W 1% 0402 SMD; Part_Type: Resistor; Manufacturer: Panasonic - ECG; Manufacturer_Part_Number: ERJ-2RKF49R9X; Component_Life_Cycle_State: CAD Reviewed; Area: 0.95; Project: KITT; Power_WV_SRF: 100; Digi_PN: 13050665
R4 R5 = 1000076: RES 0.0 OHM 1/10W 0402 SMD; Part_Type: Resistor; Manufacturer: Panasonic - ECG; Manufacturer_Part_Number: ERJ-2GE0R00X; Component_Life_Cycle_State: Proven; Area: 0.95; Project: Adjustable Foundation; Power_WV_SRF: 10; Digi_PN: 13050387
U1 = 1001439: MODULE CCWMX6 CAVITY-LESS SOM; Manufacturer: DIGI; Digi_PN: 55001818-XX; Component_Life_Cycle_State: Pending; Project: ConnectCore i.MX6x SOM

## Sheet 03 - Power, Battery charger, boot.SchDoc: Power, Boot
size A3; Author: Daniel Alesanco; Revision: 0.1; SheetNumber: 3; SheetTotal: 13; PageSetup: Record=PageOptions|CenterHorizontal=True|CenterVertical=True|PrintScale=0.70|XCorrection=1.00|YCorrection=1.00|PrintKind=0|BorderSize=5000000|LeftOffset=0|BottomOffset=0|Orientation=2|PaperLength=4200|PaperWidth=2970|Scale=100|PaperSource=7|PrintQuality=600|MediaType=1|DitherType=10|PaperKind=A4|PrintScaleMode=1
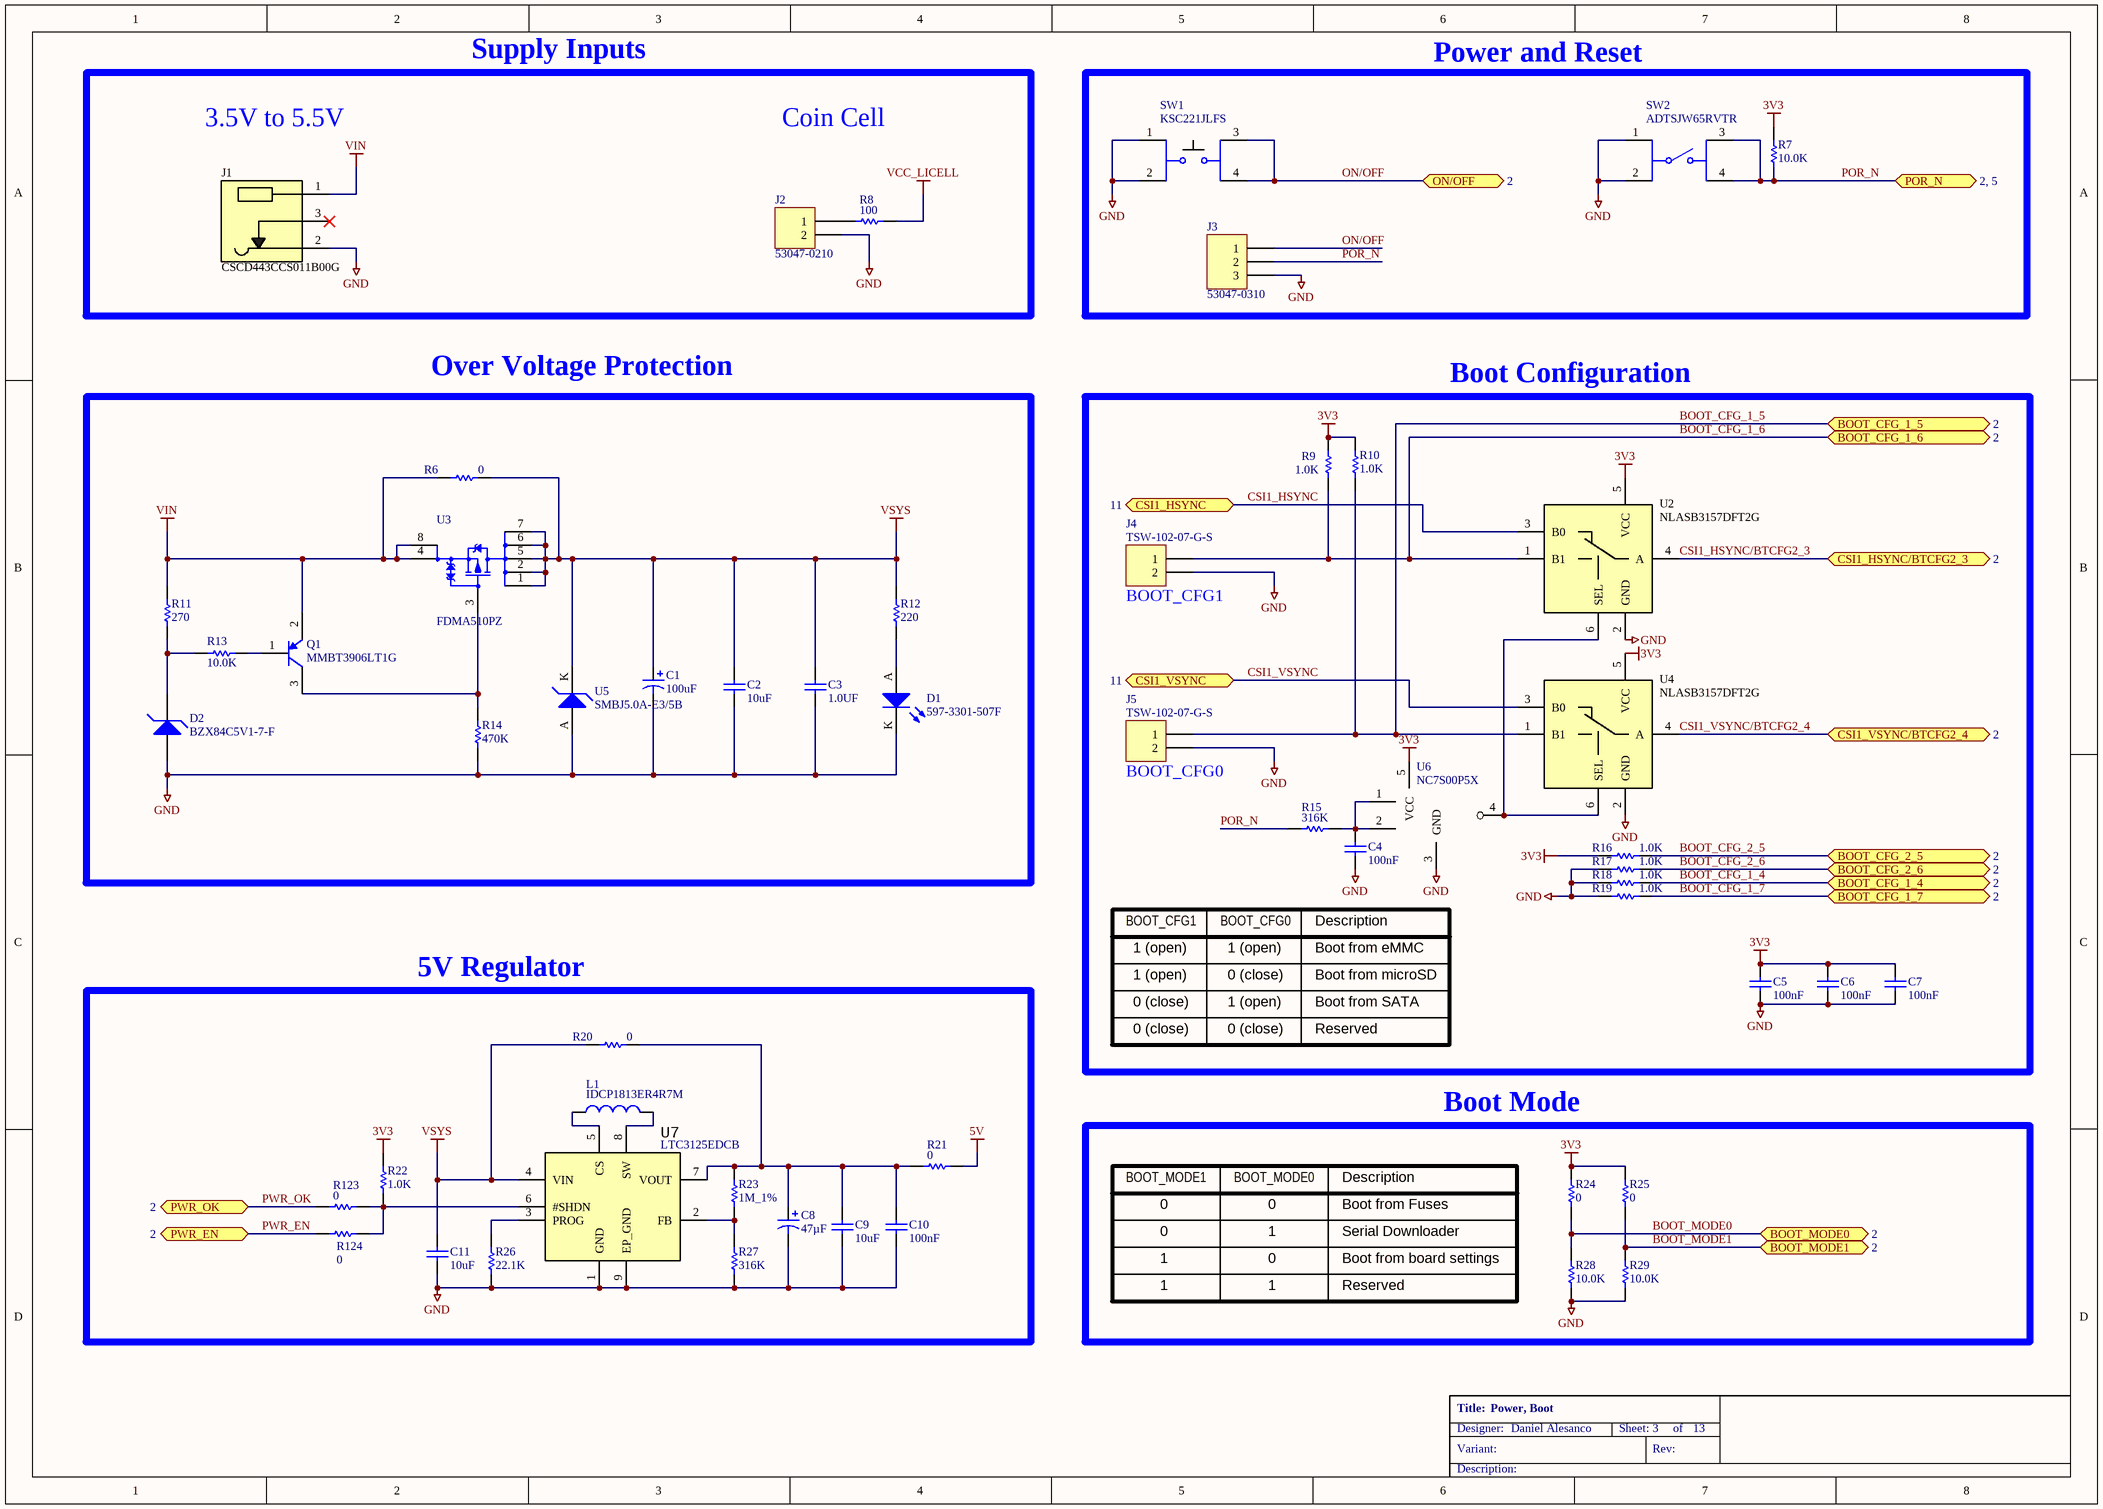
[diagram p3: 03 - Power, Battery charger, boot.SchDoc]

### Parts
C1  100uF  [CAPMP3216X120N]
C2  10uF  [CAPC1005X55N]
C3  1.0UF  [CAPC1005X55N]
C4  100nF  [CAPC1005X55N]
C5  100nF  [CAPC1005X55N]
C6  100nF  [CAPC1005X55N]
C7  100nF  [CAPC1005X55N]
C8  47µF  [CAPMP6032X280N]
C9  10uF  [CAPC1005X55N]
C10  100nF  [CAPC1005X55N]
C11  10uF  [CAPC1005X55N]
D1  597-3301-507F  [LEDM3020X130N]
D2  BZX84C5V1-7-F  [SOT95P240X110_AXK-3N]
J1  CSCD443CCS011B00G  [conn_CSCD443CCS011B00G]
J2  Manufacturer_Part_Number: 53047-0210  [MOLEX_53047-0210]  (hidden comment: 1x2P)
J3  Manufacturer_Part_Number: 53047-0310  [MOLEX_53047-0310]  (hidden comment: 1x3P)
J4  Manufacturer_Part_Number: TSW-102-07-G-S  [FCI_68002-102HLF]  (hidden comment: 1x2)
J5  Manufacturer_Part_Number: TSW-102-07-G-S  [FCI_68002-102HLF]  (hidden comment: 1x2)
L1  IDCP1813ER4R7M  [IND_SDR0403_4.5x4]
Q1  MMBT3906LT1G  [SOT95P240X110-3N]
R6  0  [RESC1005X40N]
R7  10.0K  [RESC1005X40N]
R8  100  [RESC1005X40N]
R9  1.0K  [RESC1005X40N]
R10  1.0K  [RESC1005X40N]
R11  270  [RESC1005X40N]
R12  220  [RESC1005X40N]
R13  10.0K  [RESC1005X40N]
R14  470K  [RESC1005X40N]
R15  316K  [RESC1609X55N]
R16  1.0K  [RESC1005X40N]
R17  1.0K  [RESC1005X40N]
R18  1.0K  [RESC1005X40N]
R19  1.0K  [RESC1005X40N]
R20  0  [RESC1005X40N]
R21  0  [RESC1005X40N]
R22  1.0K  [RESC1005X40N]
R23  1M_1%  [RESC1005X40N]
R24  0  [RESC1005X40N]
R25  0  [RESC1005X40N]
R26  22.1K  [RESC1005X40N]
R27  316K  [RESC1609X55N]
R28  10.0K  [RESC1005X40N]
R29  10.0K  [RESC1005X40N]
R123  0  [RESC1005X40N]
R124  0  [RESC1005X40N]
SW1  KSC221JLFS  [SW_KSC221J]
SW2  ADTSJW65RVTR  [APEM_ADTSJW65]
U2  NLASB3157DFT2G  [SOT65P210X110-6N]
U3  FDMA510PZ  [DFN200X200X80-6N]
U4  NLASB3157DFT2G  [SOT65P210X110-6N]
U5  SMBJ5.0A-E3/5B  [DIOM5436X244N]
U6  NC7S00P5X  [SOT65P210X110-5N]
U7  LTC3125EDCB  [SON45P300X200X80_175X145E-9AN]

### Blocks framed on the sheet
Supply Inputs: J1 J2 R8
Power and Reset: J3 R7 SW1 SW2
Over Voltage Protection: C1-C3 D1 D2 Q1 R6 R11-R14 U3 U5
Boot Configuration: C4-C7 J4 J5 R9 R10 R15-R19 U2 U4 U6
5V Regulator: C8-C11 L1 R20-R23 R26 R27 R123 R124 U7
Boot Mode: R24 R25 R28 R29

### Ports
BOOT_CFG_1_4 (bidir, see 2), BOOT_CFG_1_5 (bidir, see 2), BOOT_CFG_1_6 (bidir, see 2), BOOT_CFG_1_7 (bidir, see 2), BOOT_CFG_2_5 (bidir, see 2), BOOT_CFG_2_6 (bidir, see 2), BOOT_MODE0 (bidir, see 2), BOOT_MODE1 (bidir, see 2), CSI1_HSYNC (bidir, see 11), CSI1_HSYNC/BTCFG2_3 (bidir, see 2), CSI1_VSYNC (bidir, see 11), CSI1_VSYNC/BTCFG2_4 (bidir, see 2), ON/OFF (bidir, see 2), POR_N (bidir, see 2, 5), PWR_EN (bidir, see 2), PWR_OK (bidir, see 2)

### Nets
3V3: C5.2 C6.2 C7.2 R7.2 R9.2 R10.2 R16.2 R22.2 R24.2 R25.2 U2.5(VCC) U4.5(VCC) U6.5(VCC)
5V: R21.2
GND: C1.2 C2.1 C3.1 C4.1 C5.1 C6.1 C7.1 C8.2 C9.1 C10.1 C11.1 D1.K D2.A J1.2 J2.2 J3.3 J4.2 J5.2 R14.1 R17.2 R18.2 R19.2 R26.1 R27.1 R28.1 R29.1 SW1.1 SW1.2 SW2.1 SW2.2 U2.2(GND) U4.2(GND) U5.A U6.3(GND) U7.1(GND) U7.9(EP_GND)
VCC_LICELL: R8.2
VIN: J1.1 Q1.2(E) R6.1 R11.2 U3.4(S) U3.8(S)
VSYS: C1.1 C2.2 C3.2 C11.2 R6.2 R12.2 R20.1 U3.1(D) U3.2(D) U3.5(D) U3.6(D) U3.7(D) U5.K U7.4(VIN)
BOOT_CFG_1_4: R18.1 ; port BOOT_CFG_1_4
BOOT_CFG_1_5: J5.1 R10.1 U4.1(B1) ; port BOOT_CFG_1_5
BOOT_CFG_1_6: J4.1 R9.1 U2.1(B1) ; port BOOT_CFG_1_6
BOOT_CFG_1_7: R19.1 ; port BOOT_CFG_1_7
BOOT_CFG_2_5: R16.1 ; port BOOT_CFG_2_5
BOOT_CFG_2_6: R17.1 ; port BOOT_CFG_2_6
BOOT_MODE0: R24.1 R28.2 ; port BOOT_MODE0
BOOT_MODE1: R25.1 R29.2 ; port BOOT_MODE1
CSI1_HSYNC: U2.3(B0) ; port CSI1_HSYNC
CSI1_HSYNC/BTCFG2_3: U2.4(A) ; port CSI1_HSYNC/BTCFG2_3
CSI1_VSYNC: U4.3(B0) ; port CSI1_VSYNC
CSI1_VSYNC/BTCFG2_4: U4.4(A) ; port CSI1_VSYNC/BTCFG2_4
ON/OFF: J3.1 SW1.3 SW1.4 ; port ON/OFF
POR_N: J3.2 R7.1 R15.1 SW2.3 SW2.4 ; port POR_N
PWR_EN: R124.1 ; port PWR_EN
PWR_OK: R123.1 ; port PWR_OK
NetC4_2: C4.2 R15.2 U6.1(A) U6.2(B)
NetC8_1: C8.1 C9.2 C10.2 R20.2 R21.1 R23.2 U7.7(VOUT)
NetD1_A: D1.A R12.1
NetD2_K: D2.K R11.1 R13.1
NetJ2_1: J2.1 R8.1
NetL1_1: L1.1 U7.5(CS)
NetL1_2: L1.2 U7.8(SW)
NetQ1_1: Q1.1(B) R13.2
NetQ1_3: Q1.3(C) R14.2 U3.3(G)
NetR22_1: R22.1 R123.2 R124.2 U7.6(#SHDN)
NetR23_1: R23.1 R27.2 U7.2(FB)
NetR26_2: R26.2 U7.3(PROG)
NetU2_6: U2.6(SEL) U4.6(SEL) U6.4(Y)

Not connected (* = marked no-connect by the designer): J1 3*

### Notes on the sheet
- 3.5V to 5.5V
- Coin Cell
- (near J4) BOOT_CFG1
- (near J5) BOOT_CFG0
- BOOT_CFG1
- 1 (open)
- BOOT_CFG0
- 0 (close)
- Description
- Boot from eMMC
- Boot from microSD
- Boot from SATA
- Reserved
- BOOT_MODE1
- BOOT_MODE0
- 0
- 1
- Boot from Fuses
- Serial Downloader
- Boot from board settings

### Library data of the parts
C1 = 1001196: CAP TANT 100UF 6.3V 20% 1206; Part_Type: Capacitor; Manufacturer: Rohm; Manufacturer_Part_Number: TCTAL0J107M8R; Digi_PN: 14050490; Component_Life_Cycle_State: Reviewed; Area: 8.01; Project: CCWMX6_SBC board; Voltage: 6.3
C2 C9 C11 = 1001168: CAP CER 10UF 10V 20% X5R 0402; Part_Type: Capacitor; Manufacturer: Samsung; Manufacturer_Part_Number: CL05A106MP5NUNC; Digi_PN: 14050689; Component_Life_Cycle_State: Reviewed; Area: 0.95; Project: CCWMX6_SBC board; Voltage: 10
C3 = 1001167: CAP CER 1UF 10V 10% X5R 0402; Part_Type: Capacitor; Manufacturer: Murata; Manufacturer_Part_Number: GRM155R61A105KE15D; Digi_PN: 14050399; Component_Life_Cycle_State: Reviewed; Area: 0.95; Project: CCWMX6_SBC board; Voltage: 10
C4-C7 C10 = 1000006: CAP 100nF 16V 10% X7R 0402; Part_Type: Capacitor; Manufacturer: Murata; Manufacturer_Part_Number: GRM155R71C104KA88D; Component_Life_Cycle_State: CAD Reviewed; Area: 0.95; Project: KITT; Tolerance: 10; Digi_PN: 14050552
C8 = 1001164: CAP TANT 47UF 20V 10% 2413; Part_Type: Capacitor; Manufacturer: Kemet; Manufacturer_Part_Number: T491C476K020AT; Digi_PN: 14050223; Component_Life_Cycle_State: Reviewed; Area: 25.375; Project: CCWMX6_SBC board; Voltage: 20
D1 = 1001189: LED GREEN 573NM 1208 SMD; Manufacturer: Dialight; Digi_PN: 17050183; Component_Life_Cycle_State: Reviewed; Area: 6; Project: CCWMX6_SBC board
D2 = 1000824: DIODE ZENER 5.1V 300MW SOT23-3; Part_Type: Diodes; Manufacturer: Diodes, Inc.; Note: needs pins A, K; Component_Life_Cycle_State: Reviewed; Area: 10.45; Project: Dukes DMM; Digi_PN: 17050226
J1 = 1001105: DC Power Jack; Part_Type: Connector; Manufacturer: Bobbintron Electrical Corp; Digi_PN: 18000302; Component_Life_Cycle_State: Reviewed; Area: 137; Project: CCWMX6_SBC board
J2 = 1001136: CONN HEADER 2POS 1.25MM VERT TIN; Part_Type: Connector; Manufacturer: Molex; Component_Life_Cycle_State: Reviewed; Area: 13.6; Project: CCWMX6_SBC board; Digi_PN: 18050343
J3 = 1001183: CONN HEADER 3POS 1.25MM VERT TIN; Part_Type: Connector; Manufacturer: Molex; Digi_PN: 18050349; Component_Life_Cycle_State: Reviewed; Area: 17.6; Project: CCWMX6_SBC board
J4 J5 = 1001128: CONN HEADER 2POS .100" SGL GOLD; Part_Type: Connector; Manufacturer: Samtec; Digi_PN: 00120002; Component_Life_Cycle_State: Reviewed; Area: 12.9032; Project: CCWMX6_SBC board
L1 = 1001172: INDUCTOR POWER 4.7UH 1.7A SMD; Manufacturer: Vishay Dale; Digi_PN: 21000116; Component_Life_Cycle_State: Reviewed; Area: 18; Project: CCWMX6_SBC board
Q1 = 1001204: TRANS GP SS PNP 40V SOT23; Part_Type: IC; Manufacturer: On Semiconductor; Digi_PN: 17050145; Component_Life_Cycle_State: Reviewed; Area: 10.92; Project: CCWMX6_SBC board
R6 R20 R21 R24 R25 R123 R124 = 1000076: as R4 on sheet 02 - CCIMX6 Module
R7 R28 R29 = 1000537: RES 10.0K OHM 1/10W 1% 0402 SMD; Part_Type: Resistor; Manufacturer: Panasonic - ECG; Manufacturer_Part_Number: ERJ-2RKF1002X; Component_Life_Cycle_State: CAD Reviewed; Area: 0.95; Project: KITT; Power_WV_SRF: 100; Digi_PN: 13050644
R8 = 1000467: RES 100 OHM 1/10W 1% 0402 SMD; Part_Type: Resistor; Manufacturer: Panasonic - ECG; Manufacturer_Part_Number: ERJ-2RKF1000X; Component_Life_Cycle_State: CAD Reviewed; Area: 0.95; Project: KITT; Digi_PN: 13050626
R9 R10 R16-R19 R22 = 1000079: RES 1.00K OHM 1/10W 1% 0402 SMD; Part_Type: Resistor; Manufacturer: Panasonic - ECG; Manufacturer_Part_Number: ERJ-2RKF1001X; Digi_PN: 13050636; Component_Life_Cycle_State: Proven; Area: 0.95; Project: Adjustable Foundation; Power_WV_SRF: 10
R11 = 1000178: RES 270 OHM 1/10W 1% 0402 SMD; Part_Type: Resistor; Manufacturer: Panasonic - ECG; Manufacturer_Part_Number: ERJ-2RKF2700X; Digi_PN: 13050645; Component_Life_Cycle_State: CAD Reviewed; Area: 0.95; Project: SmartMeter2; Power_WV_SRF: 10
R12 = 1001154: RES 220 OHM 1/16W 1% 0402 SMD; Part_Type: Resistor; Manufacturer: Yageo; Manufacturer_Part_Number: RC0402FR-07220RL; Digi_PN: 13050623; Component_Life_Cycle_State: Reviewed; Area: 0.95; Project: CCWMX6_SBC board
R13 = 1000537: RES 10.0K OHM 1/10W 1% 0402 SMD; Part_Type: Resistor; Manufacturer: Panasonic - ECG; Manufacturer_Part_Number: ERJ-2RKF1002X; Digi_PN: 13050644; Component_Life_Cycle_State: CAD Reviewed; Area: 0.95; Project: KITT; Power_WV_SRF: 100
R14 = 1000701: RES 470K OHM 1/10W 1% 0402 SMD; Part_Type: Resistor; Manufacturer: Panasonic - ECG; Manufacturer_Part_Number: ERJ-2RKF4703X; Component_Life_Cycle_State: CAD Reviewed; Area: 0.95; Project: KITT; Power_WV_SRF: 100; Digi_PN: 13050611
R15 R27 = 1001150: RES 316K OHM 1/10W 1% 0603 SMD; Part_Type: Resistor; Manufacturer: Yageo; Manufacturer_Part_Number: RC0603FR-07316KL; Digi_PN: 13050512; Component_Life_Cycle_State: Reviewed; Area: 1.5; Project: CCWMX6_SBC board; Power_WV_SRF: 100
R23 = 1000971: RES 1.00M OHM 1/16W 1% 0402 SMD; Part_Type: Resistor; Manufacturer: Yageo; Manufacturer_Part_Number: RC0402FR-071ML; Digi_PN: 13050561; Component_Life_Cycle_State: Reviewed; Area: 0.95; Project: ConnectCore i.MX6 module; Power_WV_SRF: 63; Tolerance: 1
R26 = 1001149: RES 22.1K OHM 1/16W 1% 0402 SMD; Part_Type: Resistor; Manufacturer: Vishay Dale; Manufacturer_Part_Number: CRCW040222K1FKED; Digi_PN: 13050450; Component_Life_Cycle_State: Reviewed; Area: 0.95; Project: CCWMX6_SBC board; Power_WV_SRF: 0.063; Tolerance: ±100ppm/°C
SW1 = 1001124: SWITCH TACTILE SPST-NO 0.05A 32V; Manufacturer: ITT; Digi_PN: 22000059; Component_Life_Cycle_State: Reviewed; Area: 37; Project: CCWMX6_SBC board
SW2 = 1001171: SWITCH TACTILE SPST-NO 0.05A 12V; Manufacturer: APEM; Digi_PN: MA02993; Component_Life_Cycle_State: Created; Area: 39; Project: CCWMX6_SBC board
U2 U4 = 1001179: IC SWITCH SPDT SC88; Manufacturer: On Semiconductor; Digi_PN: 16050681; Component_Life_Cycle_State: Created; Project: CCWMX6_SBC board; Area: 4.8
U3 = 1001205: MOSFET P-CH 20V 7.8A 6-MICROFET; Part_Type: IC; Manufacturer: Fairchild Semiconductor; Digi_PN: 17050636; Component_Life_Cycle_State: Reviewed; Area: 4; Project: CCWMX6_SBC board
U5 = 1001206: TVS DIODE 5VWM 9.2VC SMB; Part_Type: Circuit Protection; Manufacturer: Vishay Semiconductors; Digi_PN: 17050018; Component_Life_Cycle_State: Reviewed; Area: 22.4; Project: CCWMX6_SBC board
U6 = 1001160: IC GATE NAND 2-INP HS LOG SC70-5; Manufacturer: Fairchild Semiconductor; Digi_PN: 16050675; Component_Life_Cycle_State: Reviewed; Area: 4.2; Project: CCWMX6_SBC board
U7 = 1001162: IC REG BOOST SYNC ADJ 1.2A 8DFN; Manufacturer: Linear Technology; Digi_PN: 16051256; Component_Life_Cycle_State: Reviewed; Area: 6; Project: CCWMX6_SBC board

## Sheet 04 - SATA, microSD.SchDoc: SATA, microSD
size A3; PageSetup: Record=PageOptions|CenterHorizontal=True|CenterVertical=True|PrintScale=0.70|XCorrection=1.00|YCorrection=1.00|PrintKind=0|BorderSize=5000000|LeftOffset=0|BottomOffset=0|Orientation=2|PaperLength=4200|PaperWidth=2970|Scale=100|PaperSource=7|PrintQuality=600|MediaType=1|DitherType=10|PaperKind=A4|PrintScaleMode=1; Author: Daniel Alesanco; SheetNumber: 4; SheetTotal: 13
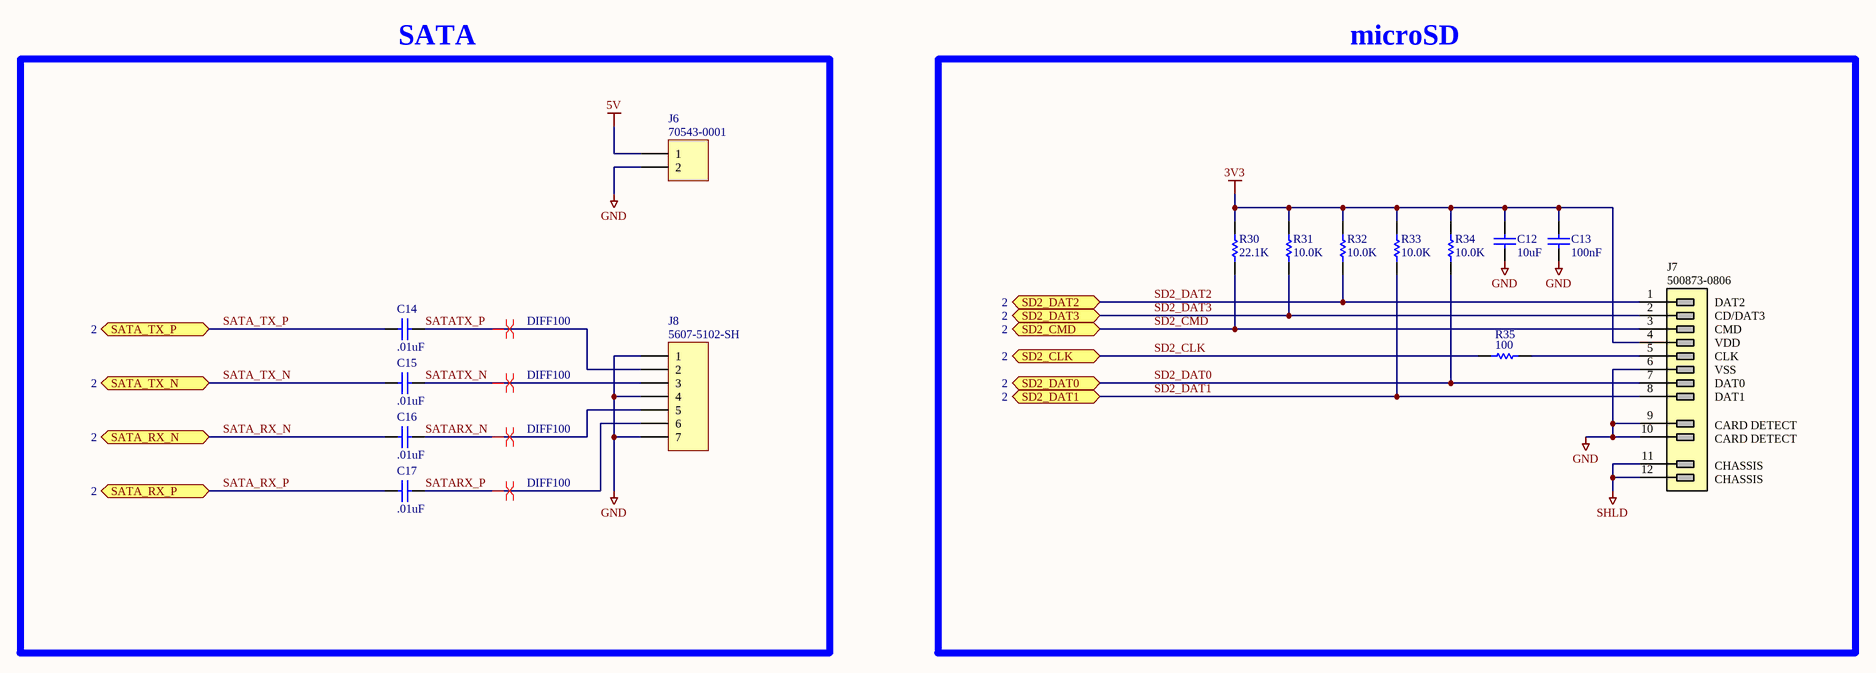
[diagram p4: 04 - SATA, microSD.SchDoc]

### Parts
C12  10uF  [CAPC1005X55N]
C13  100nF  [CAPC1005X55N]
C14  .01uF  [CAPC1005X55N]
C15  .01uF  [CAPC1005X55N]
C16  .01uF  [CAPC1005X55N]
C17  .01uF  [CAPC1005X55N]
J6  70543-0001  [CONN_70543-0001]
J7  500873-0806  [MOLEX_500873-0806]
J8  5607-5102-SH  [3M_5607-5102-SH]
R30  22.1K  [RESC1005X40N]
R31  10.0K  [RESC1005X40N]
R32  10.0K  [RESC1005X40N]
R33  10.0K  [RESC1005X40N]
R34  10.0K  [RESC1005X40N]
R35  100  [RESC1005X40N]

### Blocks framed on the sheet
SATA: C14-C17 J6 J8
microSD: C12 C13 J7 R30-R35

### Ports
SATA_RX_N (bidir, see 2), SATA_RX_P (bidir, see 2), SATA_TX_N (bidir, see 2), SATA_TX_P (bidir, see 2), SD2_CLK (bidir, see 2), SD2_CMD (bidir, see 2), SD2_DAT0 (bidir, see 2), SD2_DAT1 (bidir, see 2), SD2_DAT2 (bidir, see 2), SD2_DAT3 (bidir, see 2)

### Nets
3V3: C12.2 C13.2 J7.4 R30.2 R31.2 R32.2 R33.2 R34.2
5V: J6.1
GND: C12.1 C13.1 J6.2 J7.6 J7.9 J7.10 J8.1 J8.4 J8.7
SHLD: J7.11 J7.12
SATA_RX_N: C16.1 ; port SATA_RX_N
SATA_RX_P: C17.1 ; port SATA_RX_P
SATA_TX_N: C15.1 ; port SATA_TX_N
SATA_TX_P: C14.1 ; port SATA_TX_P
SATARX_N: C16.2 J8.5
SATARX_P: C17.2 J8.6
SATATX_N: C15.2 J8.3
SATATX_P: C14.2 J8.2
SD2_CLK: R35.1 ; port SD2_CLK
SD2_CMD: J7.3 R30.1 ; port SD2_CMD
SD2_DAT0: J7.7 R34.1 ; port SD2_DAT0
SD2_DAT1: J7.8 R33.1 ; port SD2_DAT1
SD2_DAT2: J7.1 R32.1 ; port SD2_DAT2
SD2_DAT3: J7.2 R31.1 ; port SD2_DAT3
NetJ7_5: J7.5 R35.2

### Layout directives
differential pair; net class DIFF100: SATARX_N, SATARX_P, SATATX_N, SATATX_P

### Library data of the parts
C12 = 1001168: as C2 on sheet 03 - Power, Battery charger, boot
C13 = 1000006: as C4 on sheet 03 - Power, Battery charger, boot
C14-C17 = 1001165: CAP CER 10000PF 16V 10% X7R 0402; Part_Type: Capacitor; Manufacturer: Kemet; Manufacturer_Part_Number: C0402C103K4RACTU; Digi_PN: 14050248; Component_Life_Cycle_State: Reviewed; Area: 0.95; Project: CCWMX6_SBC board; Voltage: 16
J6 = 1001106: CONN HEADER 2POS .100 VERT GOLD; Part_Type: Connector; Manufacturer: Molex; Digi_PN: 18000471; Component_Life_Cycle_State: Reviewed; Area: 36; Project: CCWMX6_SBC board
J7 = 1001118: CONN TRANSFLSH R/A PUSH-PUSH SMD; Part_Type: Connector; Manufacturer: Molex; Digi_PN: MB03015; Component_Life_Cycle_State: Reviewed; Area: 213; Project: CCWMX6_SBC board
J8 = 1001115: CONN PLUG SATA 7PS VERT PCB GOLD; Part_Type: Connector; Manufacturer: 3M; Digi_PN: 18000550; Component_Life_Cycle_State: Reviewed; Area: 102; Project: CCWMX6_SBC board
R30 = 1001149: as R26 on sheet 03 - Power, Battery charger, boot
R31-R34 = 1000537: as R7 on sheet 03 - Power, Battery charger, boot
R35 = 1000467: as R8 on sheet 03 - Power, Battery charger, boot

## Sheet 05 - JTAG, SWD, Console, UART.SchDoc: JTAG, SWD, Console, UART
size A3; PageSetup: Record=PageOptions|CenterHorizontal=True|CenterVertical=True|PrintScale=0.70|XCorrection=1.00|YCorrection=1.00|PrintKind=0|BorderSize=5000000|LeftOffset=0|BottomOffset=0|Orientation=2|PaperLength=4200|PaperWidth=2970|Scale=100|PaperSource=7|PrintQuality=600|MediaType=1|DitherType=10|PaperKind=A4|PrintScaleMode=1; Author: Daniel Alesanco; SheetNumber: 5; SheetTotal: 13
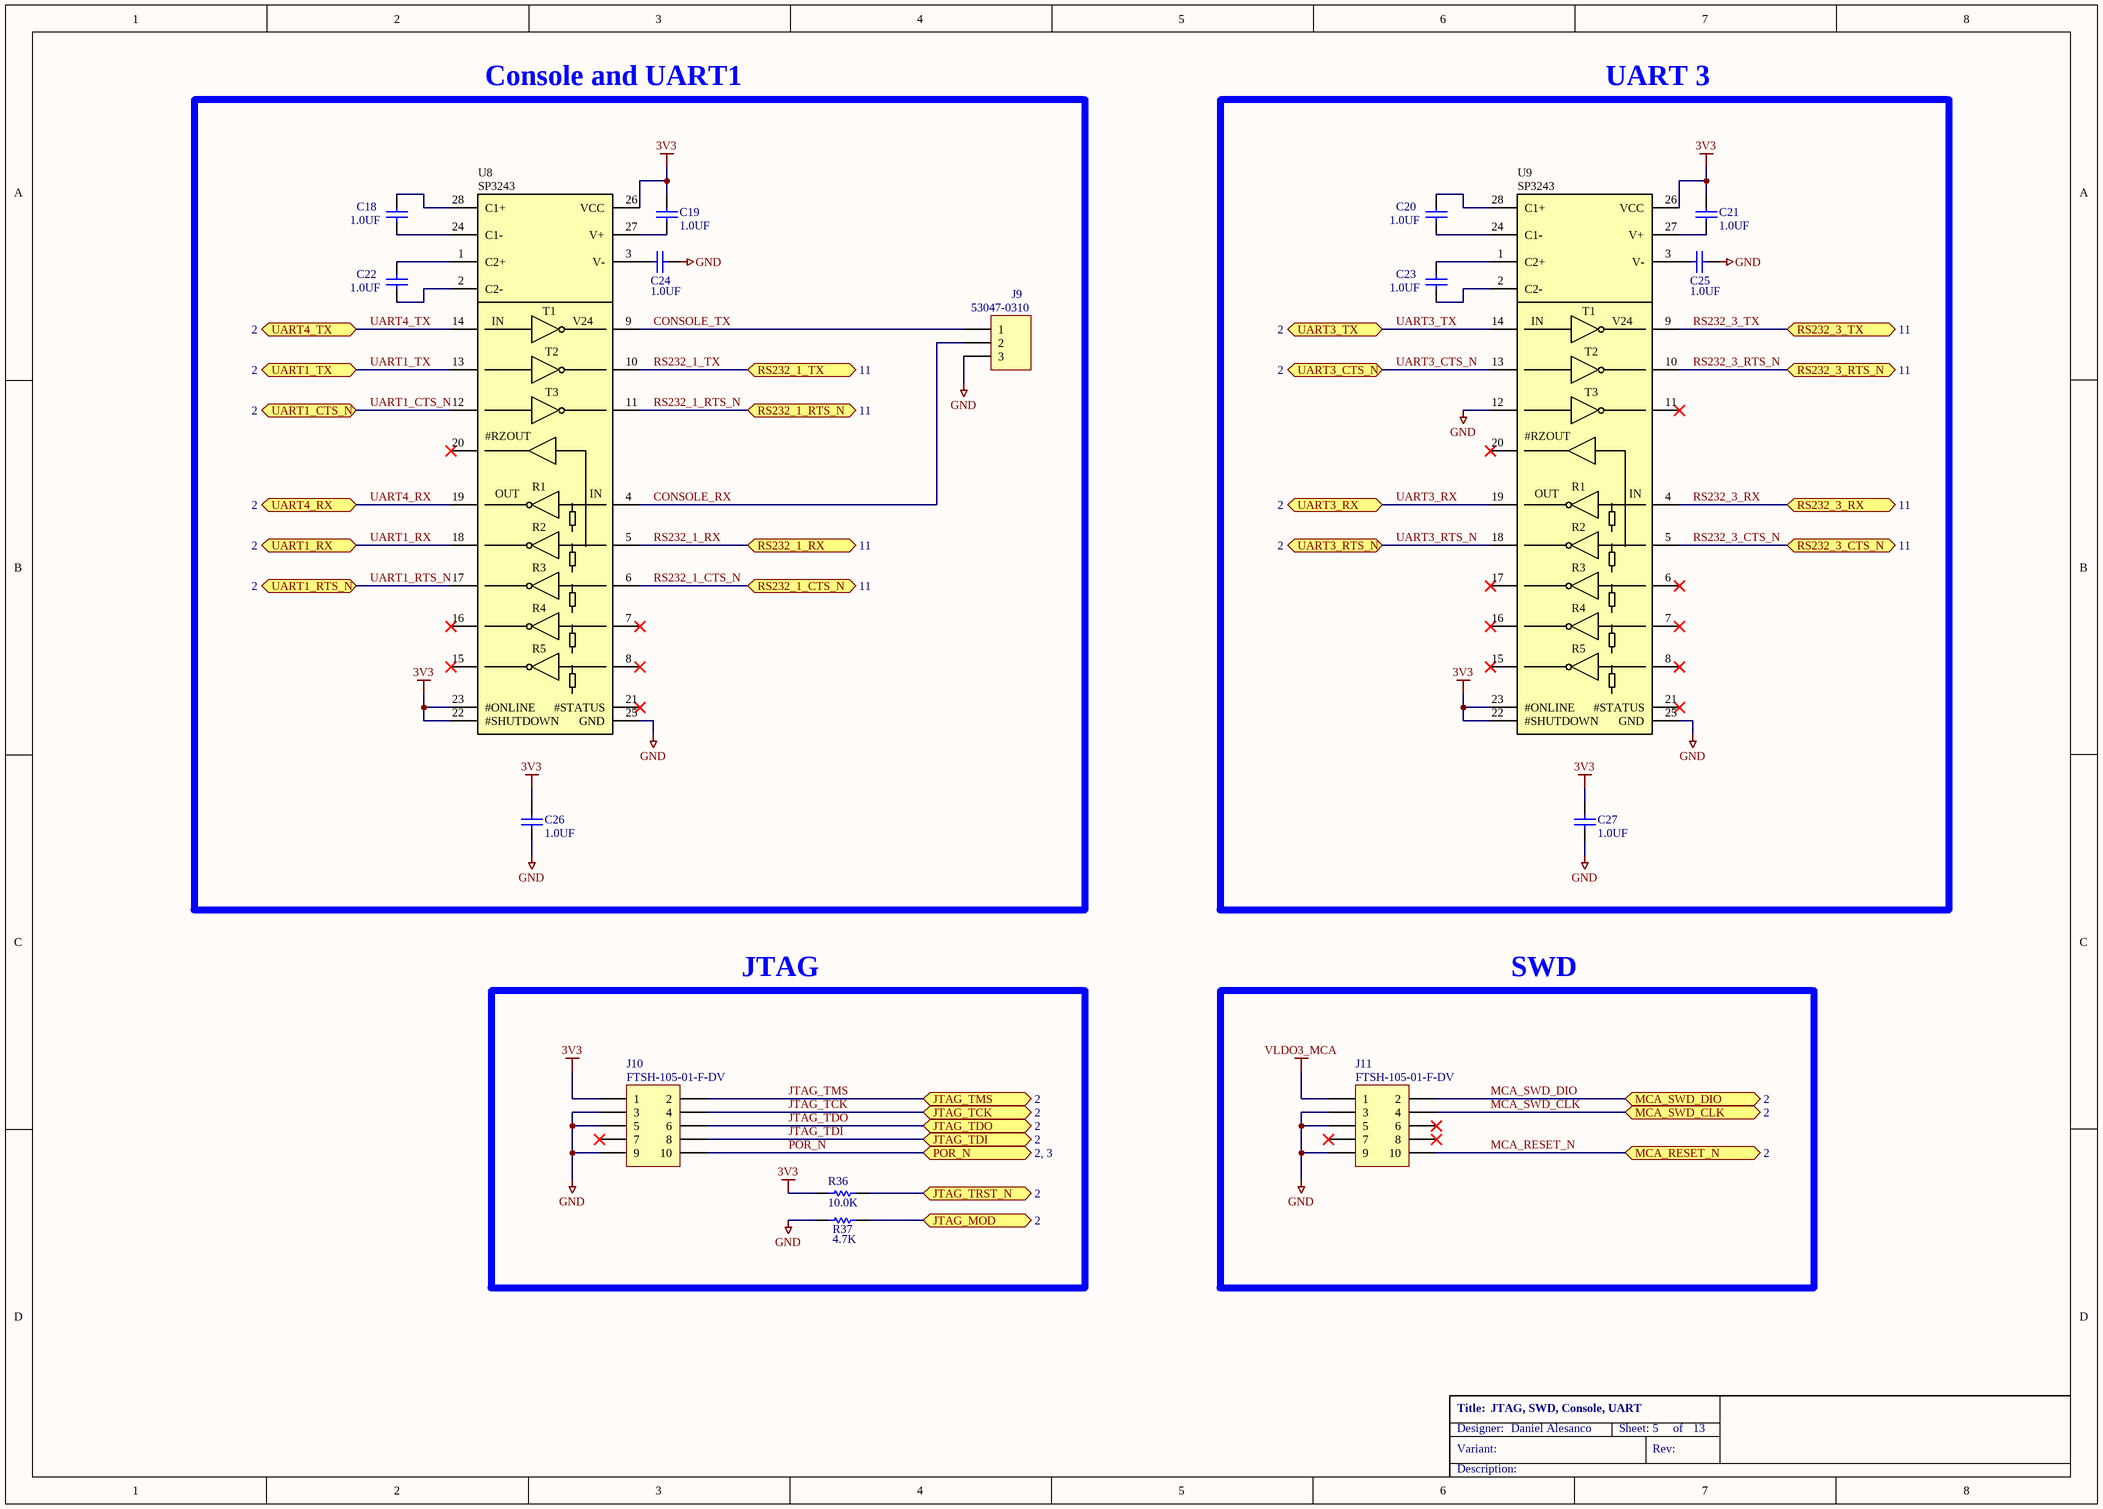
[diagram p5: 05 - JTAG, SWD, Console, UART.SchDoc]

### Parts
C18  1.0UF  [CAPC1005X55N]
C19  1.0UF  [CAPC1005X55N]
C20  1.0UF  [CAPC1005X55N]
C21  1.0UF  [CAPC1005X55N]
C22  1.0UF  [CAPC1005X55N]
C23  1.0UF  [CAPC1005X55N]
C24  1.0UF  [CAPC1005X55N]
C25  1.0UF  [CAPC1005X55N]
C26  1.0UF  [CAPC1005X55N]
C27  1.0UF  [CAPC1005X55N]
J9  Manufacturer_Part_Number: 53047-0310  [MOLEX_53047-0310]  (hidden comment: 1x3P)
J10  FTSH-105-01-F-DV  [SAMTEC_FTSH-105-01-F-DV]
J11  FTSH-105-01-F-DV  [SAMTEC_FTSH-105-01-F-DV]
R36  10.0K  [RESC1005X40N]
R37  4.7K  [RESC1005X40N]
U8  SP3243  [SOP65P780X200-28N]
U9  SP3243  [SOP65P780X200-28N]

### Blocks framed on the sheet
Console and UART1: C18 C19 C22 C24 C26 J9 U8
UART 3: C20 C21 C23 C25 C27 U9
JTAG: J10 R36 R37
SWD: J11

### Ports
JTAG_MOD (bidir, see 2), JTAG_TCK (bidir, see 2), JTAG_TDI (bidir, see 2), JTAG_TDO (bidir, see 2), JTAG_TMS (bidir, see 2), JTAG_TRST_N (bidir, see 2), MCA_RESET_N (bidir, see 2), MCA_SWD_CLK (bidir, see 2), MCA_SWD_DIO (bidir, see 2), POR_N (bidir, see 2, 3), RS232_1_CTS_N (bidir, see 11), RS232_1_RTS_N (bidir, see 11), RS232_1_RX (bidir, see 11), RS232_1_TX (bidir, see 11), RS232_3_CTS_N (bidir, see 11), RS232_3_RTS_N (bidir, see 11), RS232_3_RX (bidir, see 11), RS232_3_TX (bidir, see 11), UART1_CTS_N (bidir, see 2), UART1_RTS_N (bidir, see 2), UART1_RX (bidir, see 2), UART1_TX (bidir, see 2), UART3_CTS_N (bidir, see 2), UART3_RTS_N (bidir, see 2), UART3_RX (bidir, see 2), UART3_TX (bidir, see 2), UART4_RX (bidir, see 2), UART4_TX (bidir, see 2)

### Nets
3V3: C19.1 C21.1 C26.1 C27.1 J10.1 R36.2 U8.22(#SHUTDOWN) U8.23(#ONLINE) U8.26(VCC) U9.22(#SHUTDOWN) U9.23(#ONLINE) U9.26(VCC)
GND: C24.2 C25.2 C26.2 C27.2 J9.3 J10.3 J10.5 J10.9 J11.3 J11.5 J11.9 R37.1 U8.25(GND) U9.12(T3IN) U9.25(GND)
VLDO3_MCA: J11.1
CONSOLE_RX: J9.2 U8.4(R1IN)
CONSOLE_TX: J9.1 U8.9(T1OUT)
JTAG_MOD: R37.2 ; port JTAG_MOD
JTAG_TCK: J10.4 ; port JTAG_TCK
JTAG_TDI: J10.8 ; port JTAG_TDI
JTAG_TDO: J10.6 ; port JTAG_TDO
JTAG_TMS: J10.2 ; port JTAG_TMS
JTAG_TRST_N: R36.1 ; port JTAG_TRST_N
MCA_RESET_N: J11.10 ; port MCA_RESET_N
MCA_SWD_CLK: J11.4 ; port MCA_SWD_CLK
MCA_SWD_DIO: J11.2 ; port MCA_SWD_DIO
POR_N: J10.10 ; port POR_N
RS232_1_CTS_N: U8.6(R3IN) ; port RS232_1_CTS_N
RS232_1_RTS_N: U8.11(T3OUT) ; port RS232_1_RTS_N
RS232_1_RX: U8.5(R2IN) ; port RS232_1_RX
RS232_1_TX: U8.10(T2OUT) ; port RS232_1_TX
RS232_3_CTS_N: U9.5(R2IN) ; port RS232_3_CTS_N
RS232_3_RTS_N: U9.10(T2OUT) ; port RS232_3_RTS_N
RS232_3_RX: U9.4(R1IN) ; port RS232_3_RX
RS232_3_TX: U9.9(T1OUT) ; port RS232_3_TX
UART1_CTS_N: U8.12(T3IN) ; port UART1_CTS_N
UART1_RTS_N: U8.17(R3OUT) ; port UART1_RTS_N
UART1_RX: U8.18(R2OUT) ; port UART1_RX
UART1_TX: U8.13(T2IN) ; port UART1_TX
UART3_CTS_N: U9.13(T2IN) ; port UART3_CTS_N
UART3_RTS_N: U9.18(R2OUT) ; port UART3_RTS_N
UART3_RX: U9.19(R1OUT) ; port UART3_RX
UART3_TX: U9.14(T1IN) ; port UART3_TX
UART4_RX: U8.19(R1OUT) ; port UART4_RX
UART4_TX: U8.14(T1IN) ; port UART4_TX
NetC18_1: C18.1 U8.28(C1+)
NetC18_2: C18.2 U8.24(C1-)
NetC19_2: C19.2 U8.27(V+)
NetC20_1: C20.1 U9.28(C1+)
NetC20_2: C20.2 U9.24(C1-)
NetC21_2: C21.2 U9.27(V+)
NetC22_1: C22.1 U8.1(C2+)
NetC22_2: C22.2 U8.2(C2-)
NetC23_1: C23.1 U9.1(C2+)
NetC23_2: C23.2 U9.2(C2-)
NetC24_1: C24.1 U8.3(V-)
NetC25_1: C25.1 U9.3(V-)

Not connected (* = marked no-connect by the designer): J10 7*; J11 6* 7* 8*; U8 7(R4IN)* 8(R5IN)* 15(R5OUT)* 16(R4OUT)* 20(#R2OUT)* 21(#STATUS)*; U9 6(R3IN)* 7(R4IN)* 8(R5IN)* 11(T3OUT)* 15(R5OUT)* 16(R4OUT)* 17(R3OUT)* 20(#R2OUT)* 21(#STATUS)*

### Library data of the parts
C18-C27 = 1001167: as C3 on sheet 03 - Power, Battery charger, boot
J9 = 1001183: as J3 on sheet 03 - Power, Battery charger, boot
J10 J11 = 1000034: CONN HEADER 10POS DUAL .05" SMD; Part_Type: Connector; Manufacturer: Samtec; Component_Life_Cycle_State: Proven; Area: 43.55; Project: Adjustable Foundation; Digi_PN: 18000539
R36 = 1000537: as R7 on sheet 03 - Power, Battery charger, boot
R37 = 1000038: RES 4.7K OHM 1/10W 5% 0402 SMD; Part_Type: Resistor; Manufacturer: Panasonic - ECG; Manufacturer_Part_Number: ERJ-2GEJ472X; Component_Life_Cycle_State: Proven; Area: 0.95; Project: Adjustable Foundation; Power_WV_SRF: 100; Tolerance: 5; Digi_PN: 13050549
U8 U9 = 1001135: IC TXRX RS232 INTELLIGENT 28SSOP; Part Number: none; Manufacturer: Exar/Sipex; Manufacturer_Part_Number: SP3243EUCA-L; Digi_PN: 16050962; Component_Life_Cycle_State: Reviewed; Area: 79.56; Project: CCWMX6_SBC board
